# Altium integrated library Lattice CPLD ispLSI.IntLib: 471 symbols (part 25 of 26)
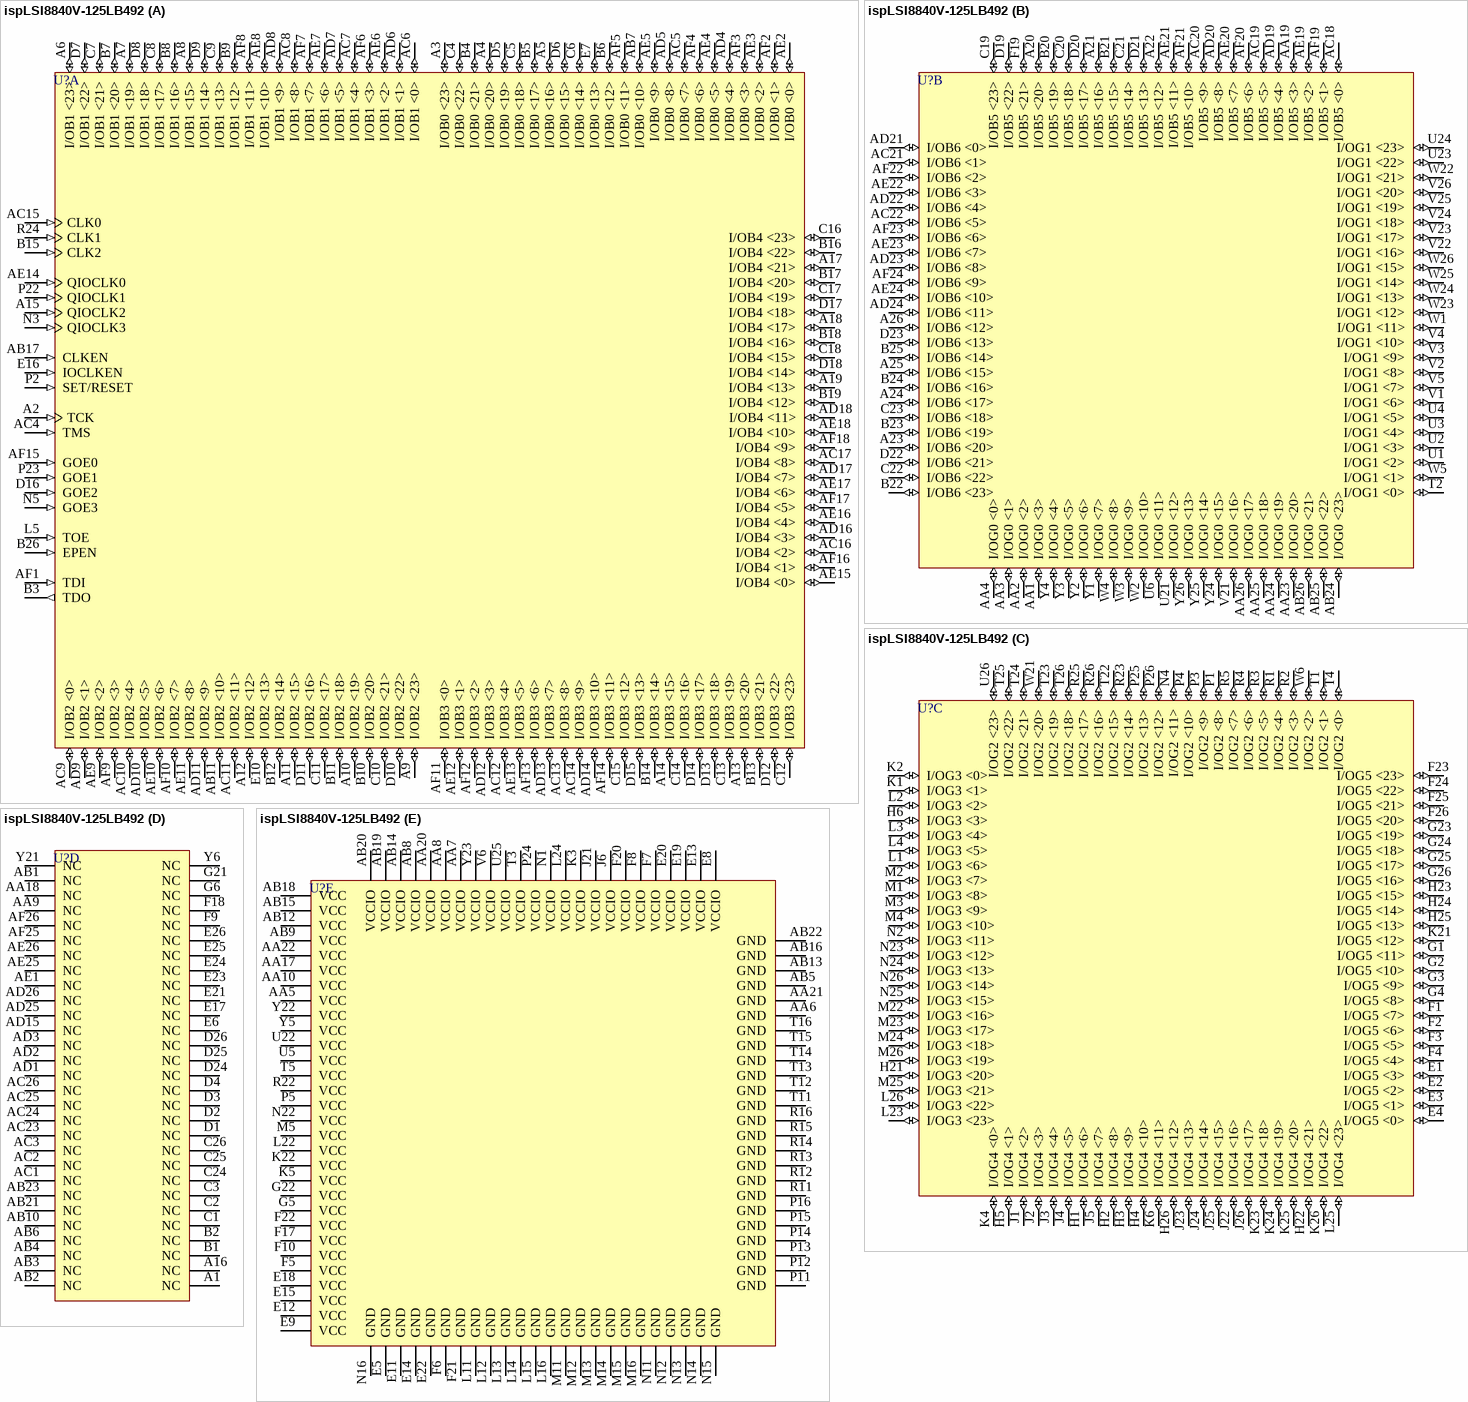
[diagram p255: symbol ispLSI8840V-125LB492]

## ispLSI8840V-125LB492
designator U?
3.3V In-System Programmable SuperBIG High Density PLD
footprint BGA492 (BGA, 492-Leads, Body 35x35mm, Pitch 1.27mm)
3D model 8840V-BGA492 (492-Ball Ball Grid Array (BGA492))
part A pins: A2 TCK (in), A3 I/OB0 <23> (io), A4 I/OB0 <20> (io), A5 I/OB0 <16> (io), A6 I/OB1 <23> (io), A7 I/OB1 <19> (io), A8 I/OB1 <15> (io), A9 I/OB2 <23> (io), A10 I/OB2 <19> (io), A11 I/OB2 <15> (io), A12 I/OB2 <12> (io), A13 I/OB3 <20> (io), A14 I/OB3 <15> (io), A15 QIOCLK2 (in), A17 I/OB4 <21> (io), A18 I/OB4 <17> (io), A19 I/OB4 <13> (io), AB7 I/OB0 <10> (io), AB11 I/OB2 <10> (io), AB17 CLKEN (in), AC4 TMS (in), AC5 I/OB0 <7> (io), AC6 I/OB1 <0> (io), AC7 I/OB1 <4> (io), AC8 I/OB1 <8> (io), AC9 I/OB2 <0> (io), AC10 I/OB2 <4> (io), AC11 I/OB2 <11> (io), AC12 I/OB3 <4> (io), AC13 I/OB3 <8> (io), AC14 I/OB3 <9> (io), AC15 CLK0 (in), AC16 I/OB4 <2> (io), AC17 I/OB4 <8> (io), AD4 I/OB0 <4> (io), AD5 I/OB0 <8> (io), AD6 I/OB1 <1> (io), AD7 I/OB1 <5> (io), AD8 I/OB1 <9> (io), AD9 I/OB2 <1> (io), AD10 I/OB2 <5> (io), AD11 I/OB2 <9> (io), AD12 I/OB3 <3> (io), AD13 I/OB3 <7> (io), AD14 I/OB3 <10> (io), AD16 I/OB4 <3> (io), AD17 I/OB4 <7> (io), AD18 I/OB4 <11> (io), AE2 I/OB0 <0> (io), AE3 I/OB0 <2> (io), AE4 I/OB0 <5> (io), AE5 I/OB0 <9> (io), AE6 I/OB1 <2> (io), AE7 I/OB1 <6> (io), AE8 I/OB1 <10> (io), AE9 I/OB2 <2> (io), AE10 I/OB2 <6> (io), AE11 I/OB2 <8> (io), AE12 I/OB3 <1> (io), AE13 I/OB3 <5> (io), AE14 QIOCLK0 (in), AE15 I/OB4 <0> (io), AE16 I/OB4 <4> (io), AE17 I/OB4 <6> (io), AE18 I/OB4 <10> (io), AF1 TDI (in), AF2 I/OB0 <1> (io), AF3 I/OB0 <3> (io), AF4 I/OB0 <6> (io), AF5 I/OB0 <11> (io), AF6 I/OB1 <3> (io), AF7 I/OB1 <7> (io), AF8 I/OB1 <11> (io), AF9 I/OB2 <3> (io), AF10 I/OB2 <7> (io), AF11 I/OB3 <0> (io), AF12 I/OB3 <2> (io), AF13 I/OB3 <6> (io), AF14 I/OB3 <11> (io), AF15 GOE0 (in), AF16 I/OB4 <1> (io), AF17 I/OB4 <5> (io), AF18 I/OB4 <9> (io), B3 TDO (out), B4 I/OB0 <21> (io), B5 I/OB0 <17> (io), B6 I/OB0 <12> (io), B7 I/OB1 <20> (io), B8 I/OB1 <16> (io), B9 I/OB1 <12> (io), B10 I/OB2 <20> (io), B11 I/OB2 <18> (io), B12 I/OB2 <14> (io), B13 I/OB3 <21> (io), B14 I/OB3 <14> (io), B15 CLK2 (in), B16 I/OB4 <22> (io), B17 I/OB4 <20> (io), B18 I/OB4 <16> (io), B19 I/OB4 <12> (io), B26 EPEN (in), C4 I/OB0 <22> (io), C5 I/OB0 <18> (io), C6 I/OB0 <14> (io), C7 I/OB1 <21> (io), C8 I/OB1 <17> (io), C9 I/OB1 <13> (io), C10 I/OB2 <21> (io), C11 I/OB2 <17> (io), C12 I/OB3 <23> (io), C13 I/OB3 <19> (io), C14 I/OB3 <16> (io), C15 I/OB3 <12> (io), C16 I/OB4 <23> (io), C17 I/OB4 <19> (io), C18 I/OB4 <15> (io), D5 I/OB0 <19> (io), D6 I/OB0 <15> (io), D7 I/OB1 <22> (io), D8 I/OB1 <18> (io), D9 I/OB1 <14> (io), D10 I/OB2 <22> (io), D11 I/OB2 <16> (io), D12 I/OB3 <22> (io), D13 I/OB3 <18> (io), D14 I/OB3 <17> (io), D15 I/OB3 <13> (io), D16 GOE2 (in), D17 I/OB4 <18> (io), D18 I/OB4 <14> (io), E7 I/OB0 <13> (io), E10 I/OB2 <13> (io), E16 IOCLKEN (in), L5 TOE (in), N3 QIOCLK3 (in), N5 GOE3 (in), P2 SET/RESET (in), P22 QIOCLK1 (in), P23 GOE1 (in), R24 CLK1 (in)
part B pins: A20 I/OB5 <20> (io), A21 I/OB5 <16> (io), A22 I/OB5 <12> (io), A23 I/OB6 <20> (io), A24 I/OB6 <17> (io), A25 I/OB6 <15> (io), A26 I/OB6 <12> (io), AA1 I/OG0 <3> (io), AA2 I/OG0 <2> (io), AA3 I/OG0 <1> (io), AA4 I/OG0 <0> (io), AA19 I/OB5 <3> (io), AA23 I/OG0 <20> (io), AA24 I/OG0 <19> (io), AA25 I/OG0 <18> (io), AA26 I/OG0 <17> (io), AB24 I/OG0 <23> (io), AB25 I/OG0 <22> (io), AB26 I/OG0 <21> (io), AC18 I/OB5 <0> (io), AC19 I/OB5 <5> (io), AC20 I/OB5 <9> (io), AC21 I/OB6 <1> (io), AC22 I/OB6 <5> (io), AD19 I/OB5 <4> (io), AD20 I/OB5 <8> (io), AD21 I/OB6 <0> (io), AD22 I/OB6 <4> (io), AD23 I/OB6 <8> (io), AD24 I/OB6 <11> (io), AE19 I/OB5 <2> (io), AE20 I/OB5 <7> (io), AE21 I/OB5 <11> (io), AE22 I/OB6 <3> (io), AE23 I/OB6 <7> (io), AE24 I/OB6 <10> (io), AF19 I/OB5 <1> (io), AF20 I/OB5 <6> (io), AF21 I/OB5 <10> (io), AF22 I/OB6 <2> (io), AF23 I/OB6 <6> (io), AF24 I/OB6 <9> (io), B20 I/OB5 <19> (io), B21 I/OB5 <15> (io), B22 I/OB6 <23> (io), B23 I/OB6 <19> (io), B24 I/OB6 <16> (io), B25 I/OB6 <14> (io), C19 I/OB5 <23> (io), C20 I/OB5 <18> (io), C21 I/OB5 <14> (io), C22 I/OB6 <22> (io), C23 I/OB6 <18> (io), D19 I/OB5 <22> (io), D20 I/OB5 <17> (io), D21 I/OB5 <13> (io), D22 I/OB6 <21> (io), D23 I/OB6 <13> (io), F19 I/OB5 <21> (io), T2 I/OG1 <0> (io), U1 I/OG1 <2> (io), U2 I/OG1 <3> (io), U3 I/OG1 <4> (io), U4 I/OG1 <5> (io), U6 I/OG0 <11> (io), U21 I/OG0 <12> (io), U23 I/OG1 <22> (io), U24 I/OG1 <23> (io), V1 I/OG1 <6> (io), V2 I/OG1 <8> (io), V3 I/OG1 <9> (io), V4 I/OG1 <10> (io), V5 I/OG1 <7> (io), V21 I/OG0 <16> (io), V22 I/OG1 <16> (io), V23 I/OG1 <17> (io), V24 I/OG1 <18> (io), V25 I/OG1 <19> (io), V26 I/OG1 <20> (io), W1 I/OG1 <11> (io), W2 I/OG0 <10> (io), W3 I/OG0 <9> (io), W4 I/OG0 <8> (io), W5 I/OG1 <1> (io), W22 I/OG1 <21> (io), W23 I/OG1 <12> (io), W24 I/OG1 <13> (io), W25 I/OG1 <14> (io), W26 I/OG1 <15> (io), Y1 I/OG0 <7> (io), Y2 I/OG0 <6> (io), Y3 I/OG0 <5> (io), Y4 I/OG0 <4> (io), Y24 I/OG0 <15> (io), Y25 I/OG0 <14> (io), Y26 I/OG0 <13> (io)
part C pins: E1 I/OG5 <3> (io), E2 I/OG5 <2> (io), E3 I/OG5 <1> (io), E4 I/OG5 <0> (io), F1 I/OG5 <7> (io), F2 I/OG5 <6> (io), F3 I/OG5 <5> (io), F4 I/OG5 <4> (io), F23 I/OG5 <23> (io), F24 I/OG5 <22> (io), F25 I/OG5 <21> (io), F26 I/OG5 <20> (io), G1 I/OG5 <11> (io), G2 I/OG5 <10> (io), G3 I/OG5 <9> (io), G4 I/OG5 <8> (io), G23 I/OG5 <19> (io), G24 I/OG5 <18> (io), G25 I/OG5 <17> (io), G26 I/OG5 <16> (io), H1 I/OG4 <6> (io), H2 I/OG4 <8> (io), H3 I/OG4 <9> (io), H4 I/OG4 <10> (io), H5 I/OG4 <1> (io), H6 I/OG3 <3> (io), H21 I/OG3 <20> (io), H22 I/OG4 <21> (io), H23 I/OG5 <15> (io), H24 I/OG5 <14> (io), H25 I/OG5 <13> (io), H26 I/OG4 <12> (io), J1 I/OG4 <2> (io), J2 I/OG4 <3> (io), J3 I/OG4 <4> (io), J4 I/OG4 <5> (io), J5 I/OG4 <7> (io), J22 I/OG4 <16> (io), J23 I/OG4 <13> (io), J24 I/OG4 <14> (io), J25 I/OG4 <15> (io), J26 I/OG4 <17> (io), K1 I/OG3 <1> (io), K2 I/OG3 <0> (io), K4 I/OG4 <0> (io), K6 I/OG4 <11> (io), K21 I/OG5 <12> (io), K23 I/OG4 <18> (io), K24 I/OG4 <19> (io), K25 I/OG4 <20> (io), K26 I/OG4 <22> (io), L1 I/OG3 <6> (io), L2 I/OG3 <2> (io), L3 I/OG3 <4> (io), L4 I/OG3 <5> (io), L23 I/OG3 <23> (io), L25 I/OG4 <23> (io), L26 I/OG3 <22> (io), M1 I/OG3 <8> (io), M2 I/OG3 <7> (io), M3 I/OG3 <9> (io), M4 I/OG3 <10> (io), M22 I/OG3 <16> (io), M23 I/OG3 <17> (io), M24 I/OG3 <18> (io), M25 I/OG3 <21> (io), M26 I/OG3 <19> (io), N2 I/OG3 <11> (io), N4 I/OG2 <11> (io), N23 I/OG3 <12> (io), N24 I/OG3 <13> (io), N25 I/OG3 <15> (io), N26 I/OG3 <14> (io), P1 I/OG2 <8> (io), P3 I/OG2 <9> (io), P4 I/OG2 <10> (io), P25 I/OG2 <13> (io), P26 I/OG2 <12> (io), R1 I/OG2 <4> (io), R2 I/OG2 <3> (io), R3 I/OG2 <5> (io), R4 I/OG2 <6> (io), R5 I/OG2 <7> (io), R23 I/OG2 <14> (io), R25 I/OG2 <17> (io), R26 I/OG2 <16> (io), T1 I/OG2 <1> (io), T4 I/OG2 <0> (io), T22 I/OG2 <15> (io), T23 I/OG2 <19> (io), T24 I/OG2 <21> (io), T25 I/OG2 <22> (io), T26 I/OG2 <18> (io), U26 I/OG2 <23> (io), W6 I/OG2 <2> (io), W21 I/OG2 <20> (io)
part D pins: A1 NC, A16 NC, AA9 NC, AA18 NC, AB1 NC, AB2 NC, AB3 NC, AB4 NC, AB6 NC, AB10 NC, AB21 NC, AB23 NC, AC1 NC, AC2 NC, AC3 NC, AC23 NC, AC24 NC, AC25 NC, AC26 NC, AD1 NC, AD2 NC, AD3 NC, AD15 NC, AD25 NC, AD26 NC, AE1 NC, AE25 NC, AE26 NC, AF25 NC, AF26 NC, B1 NC, B2 NC, C1 NC, C2 NC, C3 NC, C24 NC, C25 NC, C26 NC, D1 NC, D2 NC, D3 NC, D4 NC, D24 NC, D25 NC, D26 NC, E6 NC, E17 NC, E21 NC, E23 NC, E24 NC, E25 NC, E26 NC, F9 NC, F18 NC, G6 NC, G21 NC, Y6 NC, Y21 NC
part E pins: AA5 VCC (power), AA6 GND (power), AA7 VCCIO (power), AA8 VCCIO (power), AA10 VCC (power), AA17 VCC (power), AA20 VCCIO (power), AA21 GND (power), AA22 VCC (power), AB5 GND (power), AB8 VCCIO (power), AB9 VCC (power), AB12 VCC (power), AB13 GND (power), AB14 VCCIO (power), AB15 VCC (power), AB16 GND (power), AB18 VCC (power), AB19 VCCIO (power), AB20 VCCIO (power), AB22 GND (power), E5 GND (power), E8 VCCIO (power), E9 VCC (power), E11 GND (power), E12 VCC (power), E13 VCCIO (power), E14 GND (power), E15 VCC (power), E18 VCC (power), E19 VCCIO (power), E20 VCCIO (power), E22 GND (power), F5 VCC (power), F6 GND (power), F7 VCCIO (power), F8 VCCIO (power), F10 VCC (power), F17 VCC (power), F20 VCCIO (power), F21 GND (power), F22 VCC (power), G5 VCC (power), G22 VCC (power), J6 VCCIO (power), J21 VCCIO (power), K3 VCCIO (power), K5 VCC (power), K22 VCC (power), L11 GND (power), L12 GND (power), L13 GND (power), L14 GND (power), L15 GND (power), L16 GND (power), L22 VCC (power), L24 VCCIO (power), M5 VCC (power), M11 GND (power), M12 GND (power), M13 GND (power), M14 GND (power), M15 GND (power), M16 GND (power), N1 VCCIO (power), N11 GND (power), N12 GND (power), N13 GND (power), N14 GND (power), N15 GND (power), N16 GND (power), N22 VCC (power), P5 VCC (power), P11 GND (power), P12 GND (power), P13 GND (power), P14 GND (power), P15 GND (power), P16 GND (power), P24 VCCIO (power), R11 GND (power), R12 GND (power), R13 GND (power), R14 GND (power), R15 GND (power), R16 GND (power), R22 VCC (power), T3 VCCIO (power), T5 VCC (power), T11 GND (power), T12 GND (power), T13 GND (power), T14 GND (power), T15 GND (power), T16 GND (power), U5 VCC (power), U22 VCC (power), U25 VCCIO (power), V6 VCCIO (power), Y5 VCC (power), Y22 VCC (power), Y23 VCCIO (power)

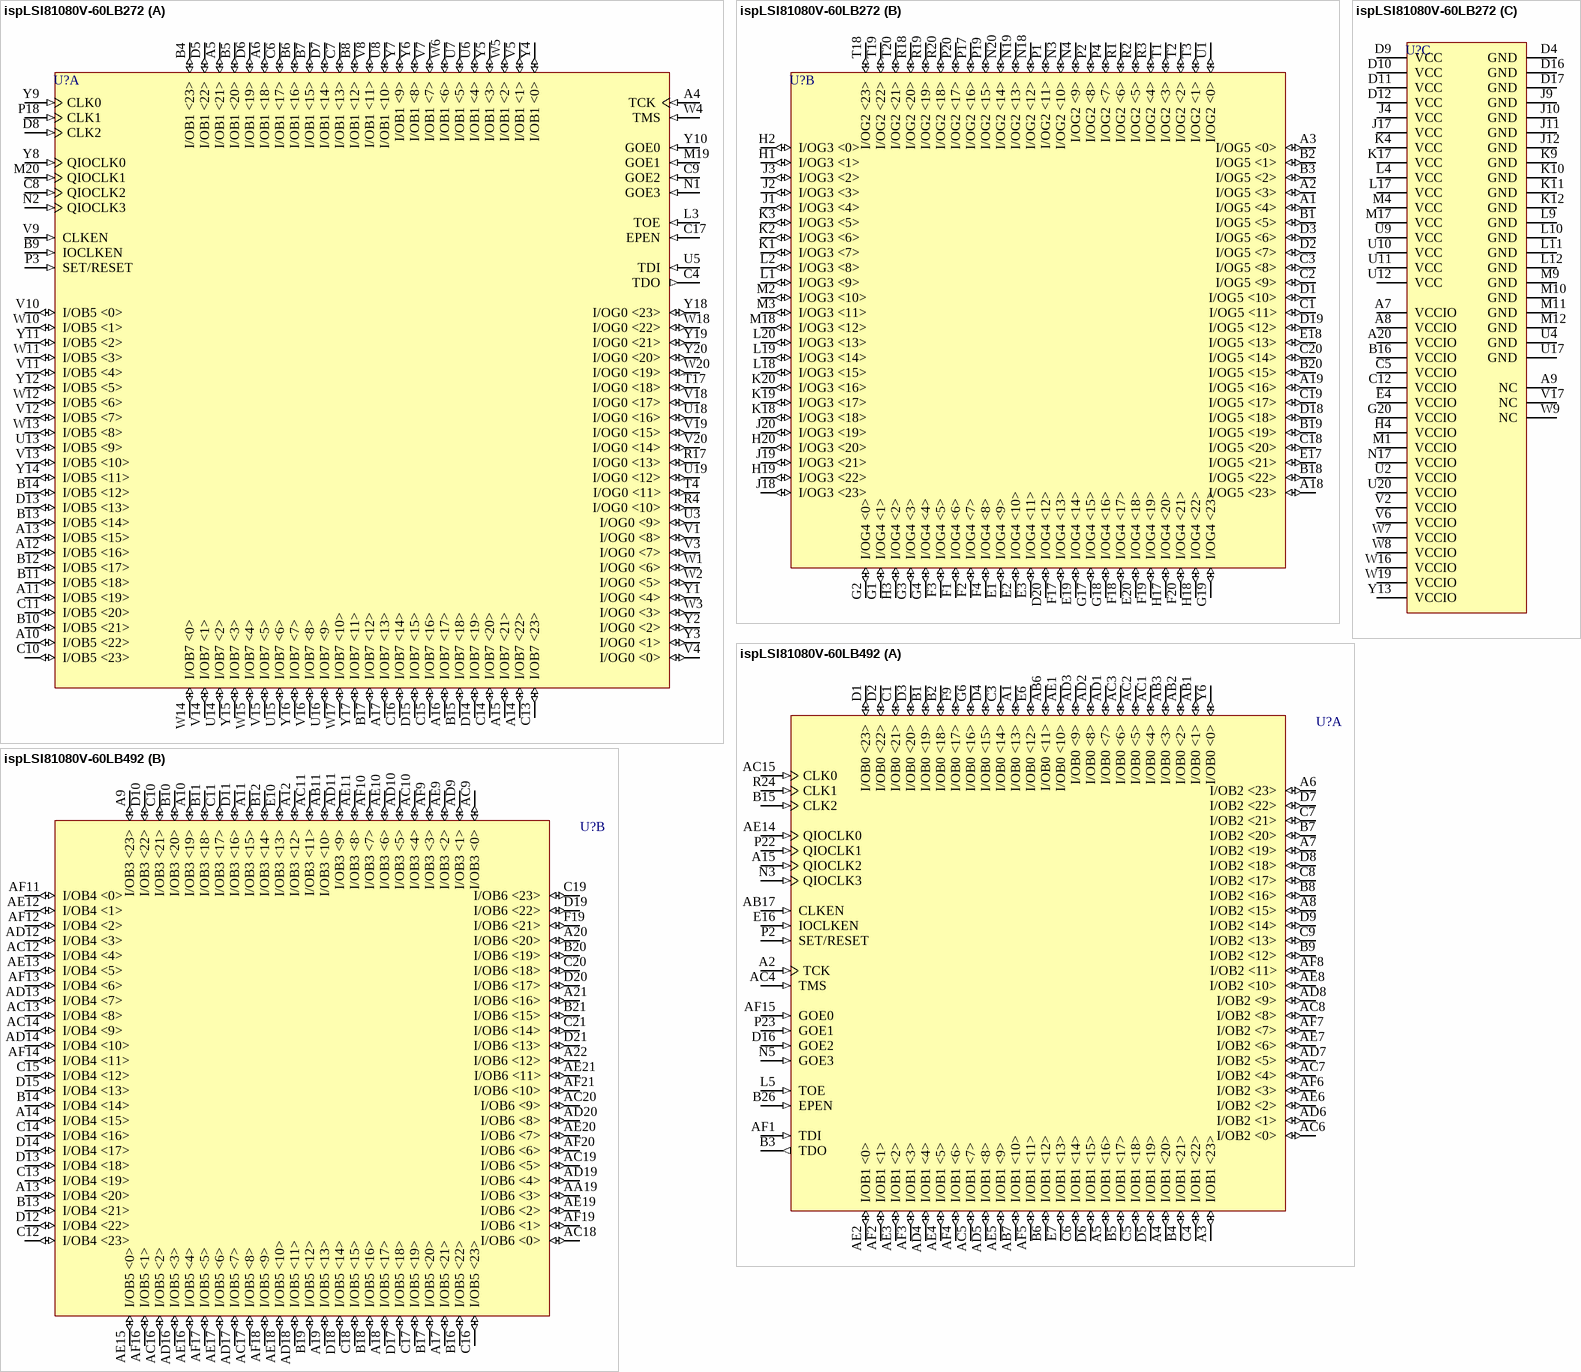
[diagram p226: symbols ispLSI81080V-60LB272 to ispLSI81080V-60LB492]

## ispLSI81080V-60LB272
designator U?
3.3V In-System Programmable SuperBIG High Density PLD
footprint BGA272 (BGA, 272-Leads, Body 27x27mm, Pitch 1.27mm)
3D model 81080V-BGA272 (272-Ball Ball Grid Array (BGA272))
part A pins: A4 TCK (in), A5 I/OB1 <21> (io), A6 I/OB1 <18> (io), A10 I/OB5 <22> (io), A11 I/OB5 <19> (io), A12 I/OB5 <16> (io), A13 I/OB5 <15> (io), A14 I/OB7 <22> (io), A15 I/OB7 <21> (io), A16 I/OB7 <17> (io), A17 I/OB7 <13> (io), B4 I/OB1 <23> (io), B5 I/OB1 <20> (io), B6 I/OB1 <16> (io), B7 I/OB1 <15> (io), B8 I/OB1 <12> (io), B9 IOCLKEN (in), B10 I/OB5 <21> (io), B11 I/OB5 <18> (io), B12 I/OB5 <17> (io), B13 I/OB5 <14> (io), B14 I/OB5 <12> (io), B15 I/OB7 <18> (io), B17 I/OB7 <12> (io), C4 TDO (out), C6 I/OB1 <17> (io), C7 I/OB1 <13> (io), C8 QIOCLK2 (in), C9 GOE2 (in), C10 I/OB5 <23> (io), C11 I/OB5 <20> (io), C13 I/OB7 <23> (io), C14 I/OB7 <20> (io), C15 I/OB7 <16> (io), C16 I/OB7 <14> (io), C17 EPEN (in), D5 I/OB1 <22> (io), D6 I/OB1 <19> (io), D7 I/OB1 <14> (io), D8 CLK2 (in), D13 I/OB5 <13> (io), D14 I/OB7 <19> (io), D15 I/OB7 <15> (io), L3 TOE (in), M19 GOE1 (in), M20 QIOCLK1 (in), N1 GOE3 (in), N2 QIOCLK3 (in), P3 SET/RESET (in), P18 CLK1 (in), R4 I/OG0 <10> (io), R17 I/OG0 <13> (io), T4 I/OG0 <11> (io), T17 I/OG0 <18> (io), U3 I/OG0 <9> (io), U5 TDI (in), U6 I/OB1 <4> (io), U7 I/OB1 <5> (io), U8 I/OB1 <10> (io), U13 I/OB5 <9> (io), U14 I/OB7 <2> (io), U15 I/OB7 <6> (io), U16 I/OB7 <9> (io), U18 I/OG0 <16> (io), U19 I/OG0 <12> (io), V1 I/OG0 <8> (io), V3 I/OG0 <7> (io), V4 I/OG0 <0> (io), V5 I/OB1 <1> (io), V7 I/OB1 <7> (io), V8 I/OB1 <11> (io), V9 CLKEN (in), V10 I/OB5 <0> (io), V11 I/OB5 <4> (io), V12 I/OB5 <7> (io), V13 I/OB5 <10> (io), V14 I/OB7 <1> (io), V15 I/OB7 <5> (io), V16 I/OB7 <8> (io), V18 I/OG0 <17> (io), V19 I/OG0 <15> (io), V20 I/OG0 <14> (io), W1 I/OG0 <6> (io), W2 I/OG0 <5> (io), W3 I/OG0 <3> (io), W4 TMS (in), W5 I/OB1 <2> (io), W6 I/OB1 <6> (io), W10 I/OB5 <1> (io), W11 I/OB5 <3> (io), W12 I/OB5 <6> (io), W13 I/OB5 <8> (io), W14 I/OB7 <0> (io), W15 I/OB7 <4> (io), W17 I/OB7 <10> (io), W18 I/OG0 <22> (io), W20 I/OG0 <19> (io), Y1 I/OG0 <4> (io), Y2 I/OG0 <2> (io), Y3 I/OG0 <1> (io), Y4 I/OB1 <0> (io), Y5 I/OB1 <3> (io), Y6 I/OB1 <8> (io), Y7 I/OB1 <9> (io), Y8 QIOCLK0 (in), Y9 CLK0 (in), Y10 GOE0 (in), Y11 I/OB5 <2> (io), Y12 I/OB5 <5> (io), Y14 I/OB5 <11> (io), Y15 I/OB7 <3> (io), Y16 I/OB7 <7> (io), Y17 I/OB7 <11> (io), Y18 I/OG0 <23> (io), Y19 I/OG0 <21> (io), Y20 I/OG0 <20> (io)
part B pins: A1 I/OG5 <4> (io), A2 I/OG5 <3> (io), A3 I/OG5 <0> (io), A18 I/OG5 <23> (io), A19 I/OG5 <16> (io), B1 I/OG5 <5> (io), B2 I/OG5 <1> (io), B3 I/OG5 <2> (io), B18 I/OG5 <22> (io), B19 I/OG5 <19> (io), B20 I/OG5 <15> (io), C1 I/OG5 <11> (io), C2 I/OG5 <9> (io), C3 I/OG5 <8> (io), C18 I/OG5 <20> (io), C19 I/OG5 <17> (io), C20 I/OG5 <14> (io), D1 I/OG5 <10> (io), D2 I/OG5 <7> (io), D3 I/OG5 <6> (io), D18 I/OG5 <18> (io), D19 I/OG5 <12> (io), D20 I/OG4 <12> (io), E1 I/OG4 <9> (io), E2 I/OG4 <10> (io), E3 I/OG4 <11> (io), E17 I/OG5 <21> (io), E18 I/OG5 <13> (io), E19 I/OG4 <14> (io), E20 I/OG4 <18> (io), F1 I/OG4 <6> (io), F2 I/OG4 <7> (io), F3 I/OG4 <5> (io), F4 I/OG4 <8> (io), F17 I/OG4 <13> (io), F18 I/OG4 <17> (io), F19 I/OG4 <19> (io), F20 I/OG4 <21> (io), G1 I/OG4 <1> (io), G2 I/OG4 <0> (io), G3 I/OG4 <3> (io), G4 I/OG4 <4> (io), G17 I/OG4 <15> (io), G18 I/OG4 <16> (io), G19 I/OG4 <23> (io), H1 I/OG3 <1> (io), H2 I/OG3 <0> (io), H3 I/OG4 <2> (io), H17 I/OG4 <20> (io), H18 I/OG4 <22> (io), H19 I/OG3 <22> (io), H20 I/OG3 <20> (io), J1 I/OG3 <4> (io), J2 I/OG3 <3> (io), J3 I/OG3 <2> (io), J18 I/OG3 <23> (io), J19 I/OG3 <21> (io), J20 I/OG3 <19> (io), K1 I/OG3 <7> (io), K2 I/OG3 <6> (io), K3 I/OG3 <5> (io), K18 I/OG3 <18> (io), K19 I/OG3 <17> (io), K20 I/OG3 <16> (io), L1 I/OG3 <9> (io), L2 I/OG3 <8> (io), L18 I/OG3 <15> (io), L19 I/OG3 <14> (io), L20 I/OG3 <13> (io), M2 I/OG3 <10> (io), M3 I/OG3 <11> (io), M18 I/OG3 <12> (io), N3 I/OG2 <10> (io), N4 I/OG2 <9> (io), N18 I/OG2 <12> (io), N19 I/OG2 <13> (io), N20 I/OG2 <14> (io), P1 I/OG2 <11> (io), P2 I/OG2 <8> (io), P4 I/OG2 <7> (io), P17 I/OG2 <16> (io), P19 I/OG2 <15> (io), P20 I/OG2 <17> (io), R1 I/OG2 <6> (io), R2 I/OG2 <5> (io), R3 I/OG2 <4> (io), R18 I/OG2 <20> (io), R19 I/OG2 <19> (io), R20 I/OG2 <18> (io), T1 I/OG2 <3> (io), T2 I/OG2 <2> (io), T3 I/OG2 <1> (io), T18 I/OG2 <23> (io), T19 I/OG2 <22> (io), T20 I/OG2 <21> (io), U1 I/OG2 <0> (io)
part C pins: A7 VCCIO (power), A8 VCCIO (power), A9 NC, A20 VCCIO (power), B16 VCCIO (power), C5 VCCIO (power), C12 VCCIO (power), D4 GND (power), D9 VCC (power), D10 VCC (power), D11 VCC (power), D12 VCC (power), D16 GND (power), D17 GND (power), E4 VCCIO (power), G20 VCCIO (power), H4 VCCIO (power), J4 VCC (power), J9 GND (power), J10 GND (power), J11 GND (power), J12 GND (power), J17 VCC (power), K4 VCC (power), K9 GND (power), K10 GND (power), K11 GND (power), K12 GND (power), K17 VCC (power), L4 VCC (power), L9 GND (power), L10 GND (power), L11 GND (power), L12 GND (power), L17 VCC (power), M1 VCCIO (power), M4 VCC (power), M9 GND (power), M10 GND (power), M11 GND (power), M12 GND (power), M17 VCC (power), N17 VCCIO (power), U2 VCCIO (power), U4 GND (power), U9 VCC (power), U10 VCC (power), U11 VCC (power), U12 VCC (power), U17 GND (power), U20 VCCIO (power), V2 VCCIO (power), V6 VCCIO (power), V17 NC, W7 VCCIO (power), W8 VCCIO (power), W9 NC, W16 VCCIO (power), W19 VCCIO (power), Y13 VCCIO (power)

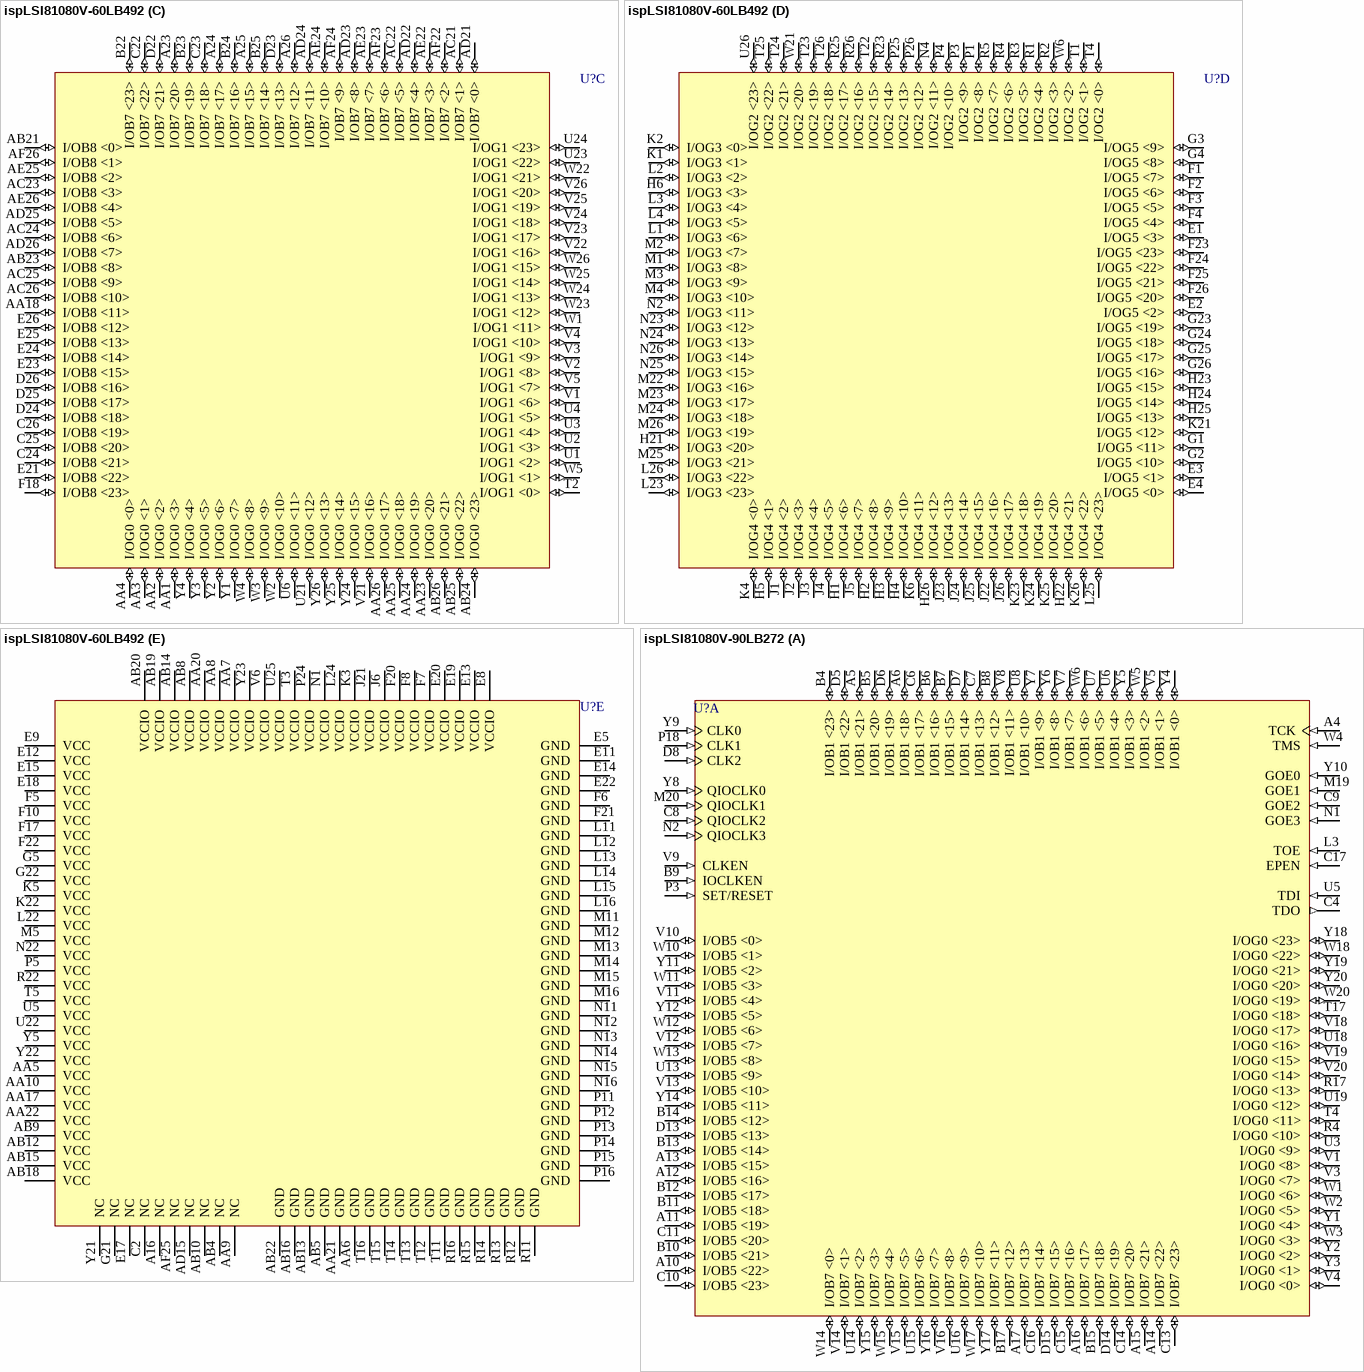
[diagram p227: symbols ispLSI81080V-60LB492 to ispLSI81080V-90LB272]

## ispLSI81080V-60LB492
designator U?
3.3V In-System Programmable SuperBIG High Density PLD
footprint BGA492 (BGA, 492-Leads, Body 35x35mm, Pitch 1.27mm)
3D model 81080V-BGA492 (492-Ball Ball Grid Array (BGA492))
part A pins: A1 I/OB0 <13> (io), A2 TCK (in), A3 I/OB1 <23> (io), A4 I/OB1 <20> (io), A5 I/OB1 <16> (io), A6 I/OB2 <23> (io), A7 I/OB2 <19> (io), A8 I/OB2 <15> (io), A15 QIOCLK2 (in), AB1 I/OB0 <1> (io), AB2 I/OB0 <2> (io), AB3 I/OB0 <3> (io), AB6 I/OB0 <11> (io), AB7 I/OB1 <10> (io), AB17 CLKEN (in), AC1 I/OB0 <4> (io), AC2 I/OB0 <5> (io), AC3 I/OB0 <6> (io), AC4 TMS (in), AC5 I/OB1 <7> (io), AC6 I/OB2 <0> (io), AC7 I/OB2 <4> (io), AC8 I/OB2 <8> (io), AC15 CLK0 (in), AD1 I/OB0 <7> (io), AD2 I/OB0 <8> (io), AD3 I/OB0 <9> (io), AD4 I/OB1 <4> (io), AD5 I/OB1 <8> (io), AD6 I/OB2 <1> (io), AD7 I/OB2 <5> (io), AD8 I/OB2 <9> (io), AE1 I/OB0 <10> (io), AE2 I/OB1 <0> (io), AE3 I/OB1 <2> (io), AE4 I/OB1 <5> (io), AE5 I/OB1 <9> (io), AE6 I/OB2 <2> (io), AE7 I/OB2 <6> (io), AE8 I/OB2 <10> (io), AE14 QIOCLK0 (in), AF1 TDI (in), AF2 I/OB1 <1> (io), AF3 I/OB1 <3> (io), AF4 I/OB1 <6> (io), AF5 I/OB1 <11> (io), AF6 I/OB2 <3> (io), AF7 I/OB2 <7> (io), AF8 I/OB2 <11> (io), AF15 GOE0 (in), B1 I/OB0 <19> (io), B2 I/OB0 <18> (io), B3 TDO (out), B4 I/OB1 <21> (io), B5 I/OB1 <17> (io), B6 I/OB1 <12> (io), B7 I/OB2 <20> (io), B8 I/OB2 <16> (io), B9 I/OB2 <12> (io), B15 CLK2 (in), B26 EPEN (in), C1 I/OB0 <21> (io), C3 I/OB0 <14> (io), C4 I/OB1 <22> (io), C5 I/OB1 <18> (io), C6 I/OB1 <14> (io), C7 I/OB2 <21> (io), C8 I/OB2 <17> (io), C9 I/OB2 <13> (io), D1 I/OB0 <23> (io), D2 I/OB0 <22> (io), D3 I/OB0 <20> (io), D4 I/OB0 <15> (io), D5 I/OB1 <19> (io), D6 I/OB1 <15> (io), D7 I/OB2 <22> (io), D8 I/OB2 <18> (io), D9 I/OB2 <14> (io), D16 GOE2 (in), E6 I/OB0 <12> (io), E7 I/OB1 <13> (io), E16 IOCLKEN (in), F9 I/OB0 <17> (io), G6 I/OB0 <16> (io), L5 TOE (in), N3 QIOCLK3 (in), N5 GOE3 (in), P2 SET/RESET (in), P22 QIOCLK1 (in), P23 GOE1 (in), R24 CLK1 (in), Y6 I/OB0 <0> (io)
part B pins: A9 I/OB3 <23> (io), A10 I/OB3 <19> (io), A11 I/OB3 <15> (io), A12 I/OB3 <12> (io), A13 I/OB4 <20> (io), A14 I/OB4 <15> (io), A17 I/OB5 <21> (io), A18 I/OB5 <17> (io), A19 I/OB5 <13> (io), A20 I/OB6 <20> (io), A21 I/OB6 <16> (io), A22 I/OB6 <12> (io), AA19 I/OB6 <3> (io), AB11 I/OB3 <10> (io), AC9 I/OB3 <0> (io), AC10 I/OB3 <4> (io), AC11 I/OB3 <11> (io), AC12 I/OB4 <4> (io), AC13 I/OB4 <8> (io), AC14 I/OB4 <9> (io), AC16 I/OB5 <2> (io), AC17 I/OB5 <8> (io), AC18 I/OB6 <0> (io), AC19 I/OB6 <5> (io), AC20 I/OB6 <9> (io), AD9 I/OB3 <1> (io), AD10 I/OB3 <5> (io), AD11 I/OB3 <9> (io), AD12 I/OB4 <3> (io), AD13 I/OB4 <7> (io), AD14 I/OB4 <10> (io), AD16 I/OB5 <3> (io), AD17 I/OB5 <7> (io), AD18 I/OB5 <11> (io), AD19 I/OB6 <4> (io), AD20 I/OB6 <8> (io), AE9 I/OB3 <2> (io), AE10 I/OB3 <6> (io), AE11 I/OB3 <8> (io), AE12 I/OB4 <1> (io), AE13 I/OB4 <5> (io), AE15 I/OB5 <0> (io), AE16 I/OB5 <4> (io), AE17 I/OB5 <6> (io), AE18 I/OB5 <10> (io), AE19 I/OB6 <2> (io), AE20 I/OB6 <7> (io), AE21 I/OB6 <11> (io), AF9 I/OB3 <3> (io), AF10 I/OB3 <7> (io), AF11 I/OB4 <0> (io), AF12 I/OB4 <2> (io), AF13 I/OB4 <6> (io), AF14 I/OB4 <11> (io), AF16 I/OB5 <1> (io), AF17 I/OB5 <5> (io), AF18 I/OB5 <9> (io), AF19 I/OB6 <1> (io), AF20 I/OB6 <6> (io), AF21 I/OB6 <10> (io), B10 I/OB3 <20> (io), B11 I/OB3 <18> (io), B12 I/OB3 <14> (io), B13 I/OB4 <21> (io), B14 I/OB4 <14> (io), B16 I/OB5 <22> (io), B17 I/OB5 <20> (io), B18 I/OB5 <16> (io), B19 I/OB5 <12> (io), B20 I/OB6 <19> (io), B21 I/OB6 <15> (io), C10 I/OB3 <21> (io), C11 I/OB3 <17> (io), C12 I/OB4 <23> (io), C13 I/OB4 <19> (io), C14 I/OB4 <16> (io), C15 I/OB4 <12> (io), C16 I/OB5 <23> (io), C17 I/OB5 <19> (io), C18 I/OB5 <15> (io), C19 I/OB6 <23> (io), C20 I/OB6 <18> (io), C21 I/OB6 <14> (io), D10 I/OB3 <22> (io), D11 I/OB3 <16> (io), D12 I/OB4 <22> (io), D13 I/OB4 <18> (io), D14 I/OB4 <17> (io), D15 I/OB4 <13> (io), D17 I/OB5 <18> (io), D18 I/OB5 <14> (io), D19 I/OB6 <22> (io), D20 I/OB6 <17> (io), D21 I/OB6 <13> (io), E10 I/OB3 <13> (io), F19 I/OB6 <21> (io)
part C pins: A23 I/OB7 <20> (io), A24 I/OB7 <17> (io), A25 I/OB7 <15> (io), A26 I/OB7 <12> (io), AA1 I/OG0 <3> (io), AA2 I/OG0 <2> (io), AA3 I/OG0 <1> (io), AA4 I/OG0 <0> (io), AA18 I/OB8 <11> (io), AA23 I/OG0 <20> (io), AA24 I/OG0 <19> (io), AA25 I/OG0 <18> (io), AA26 I/OG0 <17> (io), AB21 I/OB8 <0> (io), AB23 I/OB8 <8> (io), AB24 I/OG0 <23> (io), AB25 I/OG0 <22> (io), AB26 I/OG0 <21> (io), AC21 I/OB7 <1> (io), AC22 I/OB7 <5> (io), AC23 I/OB8 <3> (io), AC24 I/OB8 <6> (io), AC25 I/OB8 <9> (io), AC26 I/OB8 <10> (io), AD21 I/OB7 <0> (io), AD22 I/OB7 <4> (io), AD23 I/OB7 <8> (io), AD24 I/OB7 <11> (io), AD25 I/OB8 <5> (io), AD26 I/OB8 <7> (io), AE22 I/OB7 <3> (io), AE23 I/OB7 <7> (io), AE24 I/OB7 <10> (io), AE25 I/OB8 <2> (io), AE26 I/OB8 <4> (io), AF22 I/OB7 <2> (io), AF23 I/OB7 <6> (io), AF24 I/OB7 <9> (io), AF26 I/OB8 <1> (io), B22 I/OB7 <23> (io), B23 I/OB7 <19> (io), B24 I/OB7 <16> (io), B25 I/OB7 <14> (io), C22 I/OB7 <22> (io), C23 I/OB7 <18> (io), C24 I/OB8 <21> (io), C25 I/OB8 <20> (io), C26 I/OB8 <19> (io), D22 I/OB7 <21> (io), D23 I/OB7 <13> (io), D24 I/OB8 <18> (io), D25 I/OB8 <17> (io), D26 I/OB8 <16> (io), E21 I/OB8 <22> (io), E23 I/OB8 <15> (io), E24 I/OB8 <14> (io), E25 I/OB8 <13> (io), E26 I/OB8 <12> (io), F18 I/OB8 <23> (io), T2 I/OG1 <0> (io), U1 I/OG1 <2> (io), U2 I/OG1 <3> (io), U3 I/OG1 <4> (io), U4 I/OG1 <5> (io), U6 I/OG0 <11> (io), U21 I/OG0 <12> (io), U23 I/OG1 <22> (io), U24 I/OG1 <23> (io), V1 I/OG1 <6> (io), V2 I/OG1 <8> (io), V3 I/OG1 <9> (io), V4 I/OG1 <10> (io), V5 I/OG1 <7> (io), V21 I/OG0 <16> (io), V22 I/OG1 <16> (io), V23 I/OG1 <17> (io), V24 I/OG1 <18> (io), V25 I/OG1 <19> (io), V26 I/OG1 <20> (io), W1 I/OG1 <11> (io), W2 I/OG0 <10> (io), W3 I/OG0 <9> (io), W4 I/OG0 <8> (io), W5 I/OG1 <1> (io), W22 I/OG1 <21> (io), W23 I/OG1 <12> (io), W24 I/OG1 <13> (io), W25 I/OG1 <14> (io), W26 I/OG1 <15> (io), Y1 I/OG0 <7> (io), Y2 I/OG0 <6> (io), Y3 I/OG0 <5> (io), Y4 I/OG0 <4> (io), Y24 I/OG0 <15> (io), Y25 I/OG0 <14> (io), Y26 I/OG0 <13> (io)
part D pins: E1 I/OG5 <3> (io), E2 I/OG5 <2> (io), E3 I/OG5 <1> (io), E4 I/OG5 <0> (io), F1 I/OG5 <7> (io), F2 I/OG5 <6> (io), F3 I/OG5 <5> (io), F4 I/OG5 <4> (io), F23 I/OG5 <23> (io), F24 I/OG5 <22> (io), F25 I/OG5 <21> (io), F26 I/OG5 <20> (io), G1 I/OG5 <11> (io), G2 I/OG5 <10> (io), G3 I/OG5 <9> (io), G4 I/OG5 <8> (io), G23 I/OG5 <19> (io), G24 I/OG5 <18> (io), G25 I/OG5 <17> (io), G26 I/OG5 <16> (io), H1 I/OG4 <6> (io), H2 I/OG4 <8> (io), H3 I/OG4 <9> (io), H4 I/OG4 <10> (io), H5 I/OG4 <1> (io), H6 I/OG3 <3> (io), H21 I/OG3 <20> (io), H22 I/OG4 <21> (io), H23 I/OG5 <15> (io), H24 I/OG5 <14> (io), H25 I/OG5 <13> (io), H26 I/OG4 <12> (io), J1 I/OG4 <2> (io), J2 I/OG4 <3> (io), J3 I/OG4 <4> (io), J4 I/OG4 <5> (io), J5 I/OG4 <7> (io), J22 I/OG4 <16> (io), J23 I/OG4 <13> (io), J24 I/OG4 <14> (io), J25 I/OG4 <15> (io), J26 I/OG4 <17> (io), K1 I/OG3 <1> (io), K2 I/OG3 <0> (io), K4 I/OG4 <0> (io), K6 I/OG4 <11> (io), K21 I/OG5 <12> (io), K23 I/OG4 <18> (io), K24 I/OG4 <19> (io), K25 I/OG4 <20> (io), K26 I/OG4 <22> (io), L1 I/OG3 <6> (io), L2 I/OG3 <2> (io), L3 I/OG3 <4> (io), L4 I/OG3 <5> (io), L23 I/OG3 <23> (io), L25 I/OG4 <23> (io), L26 I/OG3 <22> (io), M1 I/OG3 <8> (io), M2 I/OG3 <7> (io), M3 I/OG3 <9> (io), M4 I/OG3 <10> (io), M22 I/OG3 <16> (io), M23 I/OG3 <17> (io), M24 I/OG3 <18> (io), M25 I/OG3 <21> (io), M26 I/OG3 <19> (io), N2 I/OG3 <11> (io), N4 I/OG2 <11> (io), N23 I/OG3 <12> (io), N24 I/OG3 <13> (io), N25 I/OG3 <15> (io), N26 I/OG3 <14> (io), P1 I/OG2 <8> (io), P3 I/OG2 <9> (io), P4 I/OG2 <10> (io), P25 I/OG2 <13> (io), P26 I/OG2 <12> (io), R1 I/OG2 <4> (io), R2 I/OG2 <3> (io), R3 I/OG2 <5> (io), R4 I/OG2 <6> (io), R5 I/OG2 <7> (io), R23 I/OG2 <14> (io), R25 I/OG2 <17> (io), R26 I/OG2 <16> (io), T1 I/OG2 <1> (io), T4 I/OG2 <0> (io), T22 I/OG2 <15> (io), T23 I/OG2 <19> (io), T24 I/OG2 <21> (io), T25 I/OG2 <22> (io), T26 I/OG2 <18> (io), U26 I/OG2 <23> (io), W6 I/OG2 <2> (io), W21 I/OG2 <20> (io)
part E pins: A16 NC, AA5 VCC (power), AA6 GND (power), AA7 VCCIO (power), AA8 VCCIO (power), AA9 NC, AA10 VCC (power), AA17 VCC (power), AA20 VCCIO (power), AA21 GND (power), AA22 VCC (power), AB4 NC, AB5 GND (power), AB8 VCCIO (power), AB9 VCC (power), AB10 NC, AB12 VCC (power), AB13 GND (power), AB14 VCCIO (power), AB15 VCC (power), AB16 GND (power), AB18 VCC (power), AB19 VCCIO (power), AB20 VCCIO (power), AB22 GND (power), AD15 NC, AF25 NC, C2 NC, E5 GND (power), E8 VCCIO (power), E9 VCC (power), E11 GND (power), E12 VCC (power), E13 VCCIO (power), E14 GND (power), E15 VCC (power), E17 NC, E18 VCC (power), E19 VCCIO (power), E20 VCCIO (power), E22 GND (power), F5 VCC (power), F6 GND (power), F7 VCCIO (power), F8 VCCIO (power), F10 VCC (power), F17 VCC (power), F20 VCCIO (power), F21 GND (power), F22 VCC (power), G5 VCC (power), G21 NC, G22 VCC (power), J6 VCCIO (power), J21 VCCIO (power), K3 VCCIO (power), K5 VCC (power), K22 VCC (power), L11 GND (power), L12 GND (power), L13 GND (power), L14 GND (power), L15 GND (power), L16 GND (power), L22 VCC (power), L24 VCCIO (power), M5 VCC (power), M11 GND (power), M12 GND (power), M13 GND (power), M14 GND (power), M15 GND (power), M16 GND (power), N1 VCCIO (power), N11 GND (power), N12 GND (power), N13 GND (power), N14 GND (power), N15 GND (power), N16 GND (power), N22 VCC (power), P5 VCC (power), P11 GND (power), P12 GND (power), P13 GND (power), P14 GND (power), P15 GND (power), P16 GND (power), P24 VCCIO (power), R11 GND (power), R12 GND (power), R13 GND (power), R14 GND (power), R15 GND (power), R16 GND (power), R22 VCC (power), T3 VCCIO (power), T5 VCC (power), T11 GND (power), T12 GND (power), T13 GND (power), T14 GND (power), T15 GND (power), T16 GND (power), U5 VCC (power), U22 VCC (power), U25 VCCIO (power), V6 VCCIO (power), Y5 VCC (power), Y21 NC, Y22 VCC (power), Y23 VCCIO (power)

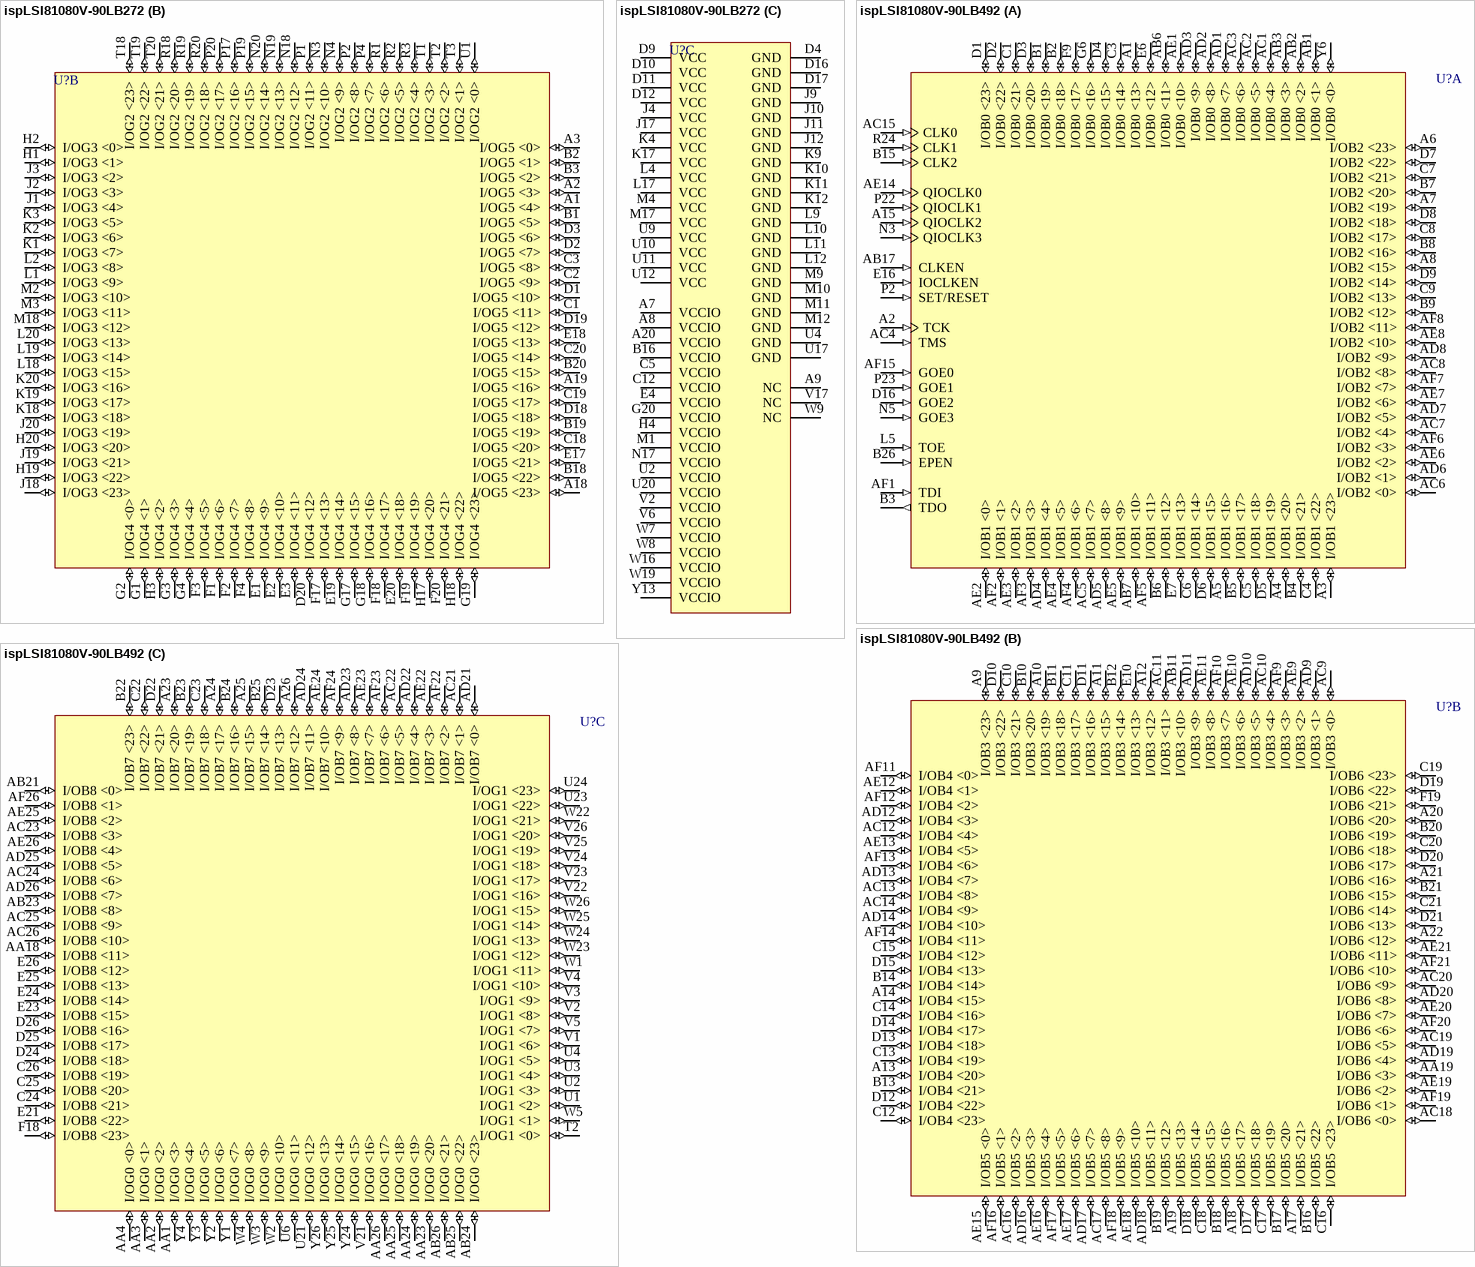
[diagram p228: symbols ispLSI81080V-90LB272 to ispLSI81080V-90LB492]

## ispLSI81080V-90LB272
designator U?
3.3V In-System Programmable SuperBIG High Density PLD
footprint BGA272 (BGA, 272-Leads, Body 27x27mm, Pitch 1.27mm)
3D model 81080V-BGA272 (272-Ball Ball Grid Array (BGA272))
part A pins: A4 TCK (in), A5 I/OB1 <21> (io), A6 I/OB1 <18> (io), A10 I/OB5 <22> (io), A11 I/OB5 <19> (io), A12 I/OB5 <16> (io), A13 I/OB5 <15> (io), A14 I/OB7 <22> (io), A15 I/OB7 <21> (io), A16 I/OB7 <17> (io), A17 I/OB7 <13> (io), B4 I/OB1 <23> (io), B5 I/OB1 <20> (io), B6 I/OB1 <16> (io), B7 I/OB1 <15> (io), B8 I/OB1 <12> (io), B9 IOCLKEN (in), B10 I/OB5 <21> (io), B11 I/OB5 <18> (io), B12 I/OB5 <17> (io), B13 I/OB5 <14> (io), B14 I/OB5 <12> (io), B15 I/OB7 <18> (io), B17 I/OB7 <12> (io), C4 TDO (out), C6 I/OB1 <17> (io), C7 I/OB1 <13> (io), C8 QIOCLK2 (in), C9 GOE2 (in), C10 I/OB5 <23> (io), C11 I/OB5 <20> (io), C13 I/OB7 <23> (io), C14 I/OB7 <20> (io), C15 I/OB7 <16> (io), C16 I/OB7 <14> (io), C17 EPEN (in), D5 I/OB1 <22> (io), D6 I/OB1 <19> (io), D7 I/OB1 <14> (io), D8 CLK2 (in), D13 I/OB5 <13> (io), D14 I/OB7 <19> (io), D15 I/OB7 <15> (io), L3 TOE (in), M19 GOE1 (in), M20 QIOCLK1 (in), N1 GOE3 (in), N2 QIOCLK3 (in), P3 SET/RESET (in), P18 CLK1 (in), R4 I/OG0 <10> (io), R17 I/OG0 <13> (io), T4 I/OG0 <11> (io), T17 I/OG0 <18> (io), U3 I/OG0 <9> (io), U5 TDI (in), U6 I/OB1 <4> (io), U7 I/OB1 <5> (io), U8 I/OB1 <10> (io), U13 I/OB5 <9> (io), U14 I/OB7 <2> (io), U15 I/OB7 <6> (io), U16 I/OB7 <9> (io), U18 I/OG0 <16> (io), U19 I/OG0 <12> (io), V1 I/OG0 <8> (io), V3 I/OG0 <7> (io), V4 I/OG0 <0> (io), V5 I/OB1 <1> (io), V7 I/OB1 <7> (io), V8 I/OB1 <11> (io), V9 CLKEN (in), V10 I/OB5 <0> (io), V11 I/OB5 <4> (io), V12 I/OB5 <7> (io), V13 I/OB5 <10> (io), V14 I/OB7 <1> (io), V15 I/OB7 <5> (io), V16 I/OB7 <8> (io), V18 I/OG0 <17> (io), V19 I/OG0 <15> (io), V20 I/OG0 <14> (io), W1 I/OG0 <6> (io), W2 I/OG0 <5> (io), W3 I/OG0 <3> (io), W4 TMS (in), W5 I/OB1 <2> (io), W6 I/OB1 <6> (io), W10 I/OB5 <1> (io), W11 I/OB5 <3> (io), W12 I/OB5 <6> (io), W13 I/OB5 <8> (io), W14 I/OB7 <0> (io), W15 I/OB7 <4> (io), W17 I/OB7 <10> (io), W18 I/OG0 <22> (io), W20 I/OG0 <19> (io), Y1 I/OG0 <4> (io), Y2 I/OG0 <2> (io), Y3 I/OG0 <1> (io), Y4 I/OB1 <0> (io), Y5 I/OB1 <3> (io), Y6 I/OB1 <8> (io), Y7 I/OB1 <9> (io), Y8 QIOCLK0 (in), Y9 CLK0 (in), Y10 GOE0 (in), Y11 I/OB5 <2> (io), Y12 I/OB5 <5> (io), Y14 I/OB5 <11> (io), Y15 I/OB7 <3> (io), Y16 I/OB7 <7> (io), Y17 I/OB7 <11> (io), Y18 I/OG0 <23> (io), Y19 I/OG0 <21> (io), Y20 I/OG0 <20> (io)
part B pins: A1 I/OG5 <4> (io), A2 I/OG5 <3> (io), A3 I/OG5 <0> (io), A18 I/OG5 <23> (io), A19 I/OG5 <16> (io), B1 I/OG5 <5> (io), B2 I/OG5 <1> (io), B3 I/OG5 <2> (io), B18 I/OG5 <22> (io), B19 I/OG5 <19> (io), B20 I/OG5 <15> (io), C1 I/OG5 <11> (io), C2 I/OG5 <9> (io), C3 I/OG5 <8> (io), C18 I/OG5 <20> (io), C19 I/OG5 <17> (io), C20 I/OG5 <14> (io), D1 I/OG5 <10> (io), D2 I/OG5 <7> (io), D3 I/OG5 <6> (io), D18 I/OG5 <18> (io), D19 I/OG5 <12> (io), D20 I/OG4 <12> (io), E1 I/OG4 <9> (io), E2 I/OG4 <10> (io), E3 I/OG4 <11> (io), E17 I/OG5 <21> (io), E18 I/OG5 <13> (io), E19 I/OG4 <14> (io), E20 I/OG4 <18> (io), F1 I/OG4 <6> (io), F2 I/OG4 <7> (io), F3 I/OG4 <5> (io), F4 I/OG4 <8> (io), F17 I/OG4 <13> (io), F18 I/OG4 <17> (io), F19 I/OG4 <19> (io), F20 I/OG4 <21> (io), G1 I/OG4 <1> (io), G2 I/OG4 <0> (io), G3 I/OG4 <3> (io), G4 I/OG4 <4> (io), G17 I/OG4 <15> (io), G18 I/OG4 <16> (io), G19 I/OG4 <23> (io), H1 I/OG3 <1> (io), H2 I/OG3 <0> (io), H3 I/OG4 <2> (io), H17 I/OG4 <20> (io), H18 I/OG4 <22> (io), H19 I/OG3 <22> (io), H20 I/OG3 <20> (io), J1 I/OG3 <4> (io), J2 I/OG3 <3> (io), J3 I/OG3 <2> (io), J18 I/OG3 <23> (io), J19 I/OG3 <21> (io), J20 I/OG3 <19> (io), K1 I/OG3 <7> (io), K2 I/OG3 <6> (io), K3 I/OG3 <5> (io), K18 I/OG3 <18> (io), K19 I/OG3 <17> (io), K20 I/OG3 <16> (io), L1 I/OG3 <9> (io), L2 I/OG3 <8> (io), L18 I/OG3 <15> (io), L19 I/OG3 <14> (io), L20 I/OG3 <13> (io), M2 I/OG3 <10> (io), M3 I/OG3 <11> (io), M18 I/OG3 <12> (io), N3 I/OG2 <10> (io), N4 I/OG2 <9> (io), N18 I/OG2 <12> (io), N19 I/OG2 <13> (io), N20 I/OG2 <14> (io), P1 I/OG2 <11> (io), P2 I/OG2 <8> (io), P4 I/OG2 <7> (io), P17 I/OG2 <16> (io), P19 I/OG2 <15> (io), P20 I/OG2 <17> (io), R1 I/OG2 <6> (io), R2 I/OG2 <5> (io), R3 I/OG2 <4> (io), R18 I/OG2 <20> (io), R19 I/OG2 <19> (io), R20 I/OG2 <18> (io), T1 I/OG2 <3> (io), T2 I/OG2 <2> (io), T3 I/OG2 <1> (io), T18 I/OG2 <23> (io), T19 I/OG2 <22> (io), T20 I/OG2 <21> (io), U1 I/OG2 <0> (io)
part C pins: A7 VCCIO (power), A8 VCCIO (power), A9 NC, A20 VCCIO (power), B16 VCCIO (power), C5 VCCIO (power), C12 VCCIO (power), D4 GND (power), D9 VCC (power), D10 VCC (power), D11 VCC (power), D12 VCC (power), D16 GND (power), D17 GND (power), E4 VCCIO (power), G20 VCCIO (power), H4 VCCIO (power), J4 VCC (power), J9 GND (power), J10 GND (power), J11 GND (power), J12 GND (power), J17 VCC (power), K4 VCC (power), K9 GND (power), K10 GND (power), K11 GND (power), K12 GND (power), K17 VCC (power), L4 VCC (power), L9 GND (power), L10 GND (power), L11 GND (power), L12 GND (power), L17 VCC (power), M1 VCCIO (power), M4 VCC (power), M9 GND (power), M10 GND (power), M11 GND (power), M12 GND (power), M17 VCC (power), N17 VCCIO (power), U2 VCCIO (power), U4 GND (power), U9 VCC (power), U10 VCC (power), U11 VCC (power), U12 VCC (power), U17 GND (power), U20 VCCIO (power), V2 VCCIO (power), V6 VCCIO (power), V17 NC, W7 VCCIO (power), W8 VCCIO (power), W9 NC, W16 VCCIO (power), W19 VCCIO (power), Y13 VCCIO (power)

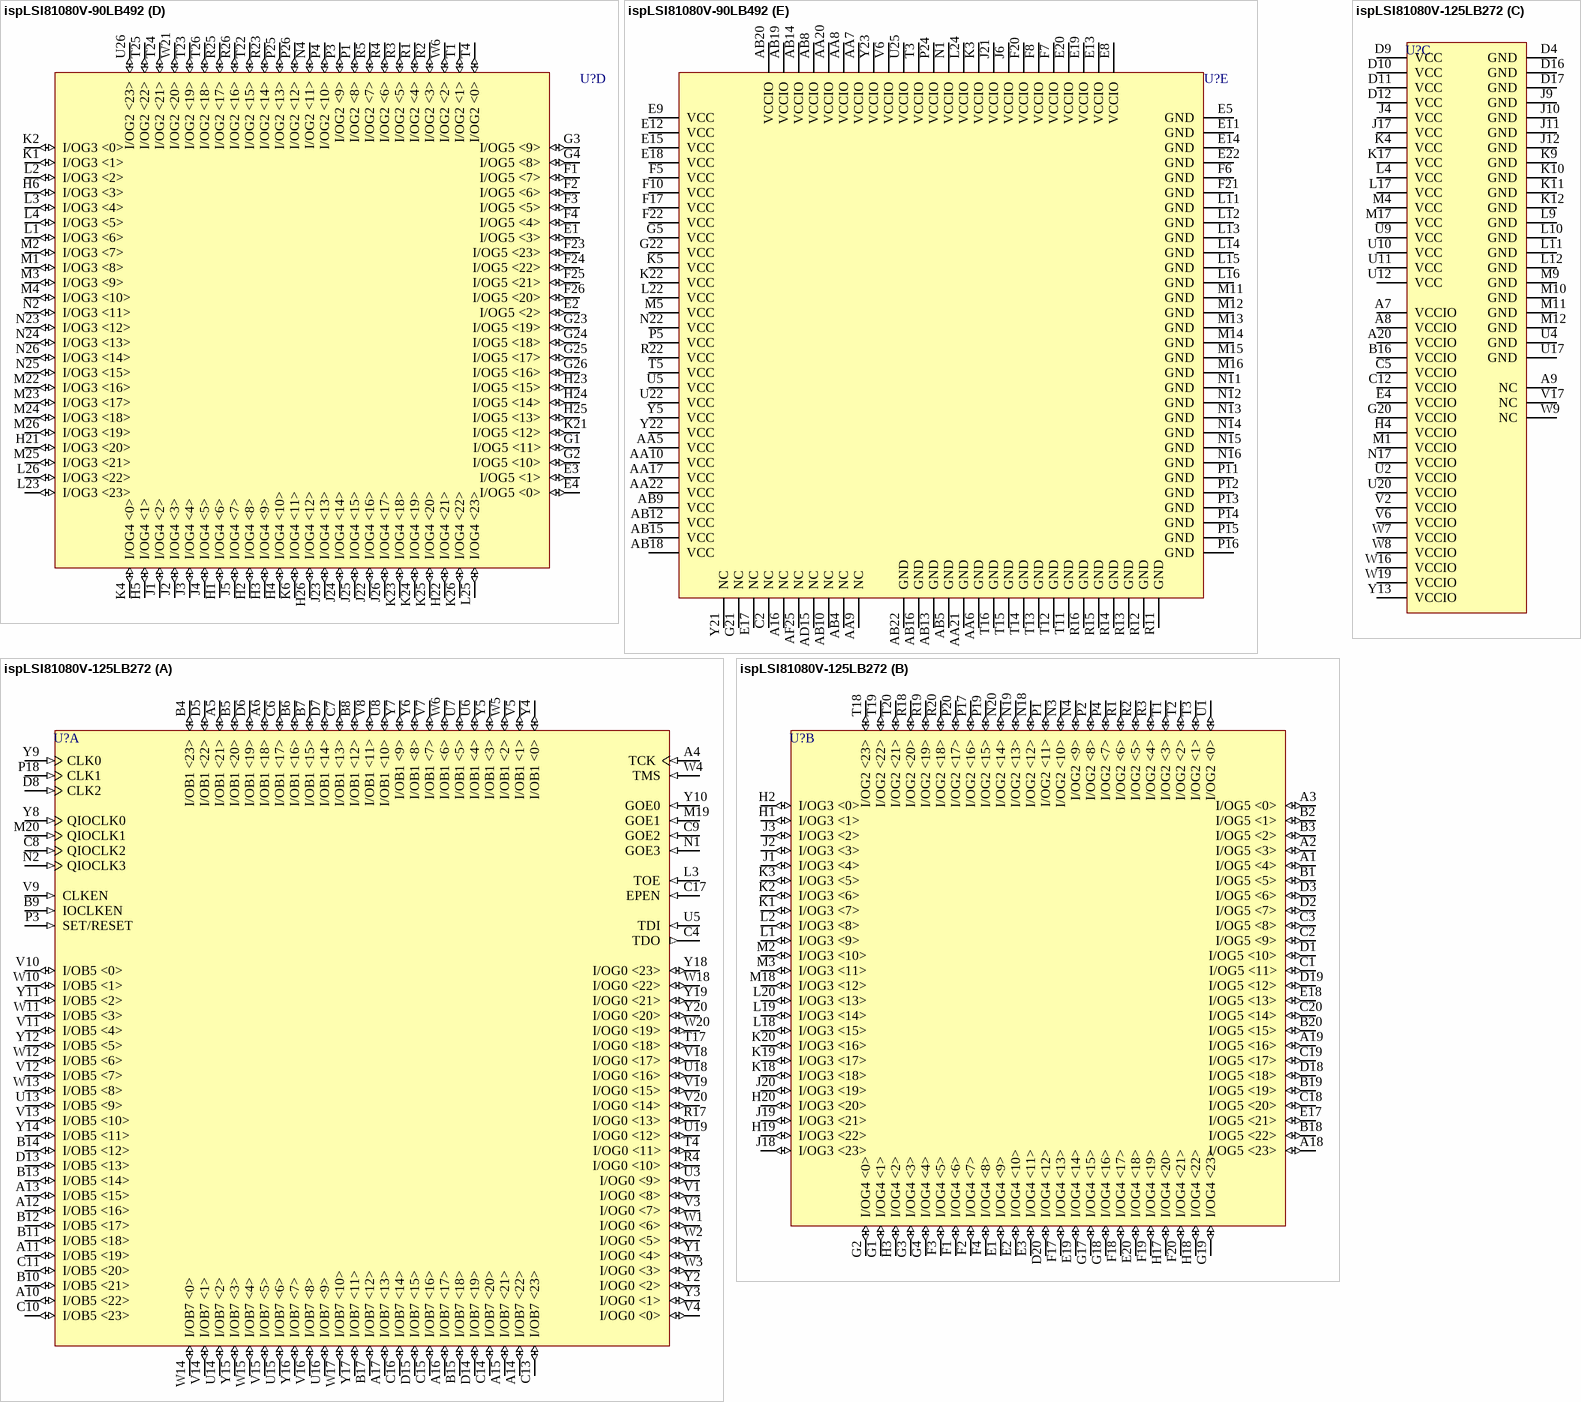
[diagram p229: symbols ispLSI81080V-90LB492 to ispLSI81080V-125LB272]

## ispLSI81080V-90LB492
designator U?
3.3V In-System Programmable SuperBIG High Density PLD
footprint BGA492 (BGA, 492-Leads, Body 35x35mm, Pitch 1.27mm)
3D model 81080V-BGA492 (492-Ball Ball Grid Array (BGA492))
part A pins: A1 I/OB0 <13> (io), A2 TCK (in), A3 I/OB1 <23> (io), A4 I/OB1 <20> (io), A5 I/OB1 <16> (io), A6 I/OB2 <23> (io), A7 I/OB2 <19> (io), A8 I/OB2 <15> (io), A15 QIOCLK2 (in), AB1 I/OB0 <1> (io), AB2 I/OB0 <2> (io), AB3 I/OB0 <3> (io), AB6 I/OB0 <11> (io), AB7 I/OB1 <10> (io), AB17 CLKEN (in), AC1 I/OB0 <4> (io), AC2 I/OB0 <5> (io), AC3 I/OB0 <6> (io), AC4 TMS (in), AC5 I/OB1 <7> (io), AC6 I/OB2 <0> (io), AC7 I/OB2 <4> (io), AC8 I/OB2 <8> (io), AC15 CLK0 (in), AD1 I/OB0 <7> (io), AD2 I/OB0 <8> (io), AD3 I/OB0 <9> (io), AD4 I/OB1 <4> (io), AD5 I/OB1 <8> (io), AD6 I/OB2 <1> (io), AD7 I/OB2 <5> (io), AD8 I/OB2 <9> (io), AE1 I/OB0 <10> (io), AE2 I/OB1 <0> (io), AE3 I/OB1 <2> (io), AE4 I/OB1 <5> (io), AE5 I/OB1 <9> (io), AE6 I/OB2 <2> (io), AE7 I/OB2 <6> (io), AE8 I/OB2 <10> (io), AE14 QIOCLK0 (in), AF1 TDI (in), AF2 I/OB1 <1> (io), AF3 I/OB1 <3> (io), AF4 I/OB1 <6> (io), AF5 I/OB1 <11> (io), AF6 I/OB2 <3> (io), AF7 I/OB2 <7> (io), AF8 I/OB2 <11> (io), AF15 GOE0 (in), B1 I/OB0 <19> (io), B2 I/OB0 <18> (io), B3 TDO (out), B4 I/OB1 <21> (io), B5 I/OB1 <17> (io), B6 I/OB1 <12> (io), B7 I/OB2 <20> (io), B8 I/OB2 <16> (io), B9 I/OB2 <12> (io), B15 CLK2 (in), B26 EPEN (in), C1 I/OB0 <21> (io), C3 I/OB0 <14> (io), C4 I/OB1 <22> (io), C5 I/OB1 <18> (io), C6 I/OB1 <14> (io), C7 I/OB2 <21> (io), C8 I/OB2 <17> (io), C9 I/OB2 <13> (io), D1 I/OB0 <23> (io), D2 I/OB0 <22> (io), D3 I/OB0 <20> (io), D4 I/OB0 <15> (io), D5 I/OB1 <19> (io), D6 I/OB1 <15> (io), D7 I/OB2 <22> (io), D8 I/OB2 <18> (io), D9 I/OB2 <14> (io), D16 GOE2 (in), E6 I/OB0 <12> (io), E7 I/OB1 <13> (io), E16 IOCLKEN (in), F9 I/OB0 <17> (io), G6 I/OB0 <16> (io), L5 TOE (in), N3 QIOCLK3 (in), N5 GOE3 (in), P2 SET/RESET (in), P22 QIOCLK1 (in), P23 GOE1 (in), R24 CLK1 (in), Y6 I/OB0 <0> (io)
part B pins: A9 I/OB3 <23> (io), A10 I/OB3 <19> (io), A11 I/OB3 <15> (io), A12 I/OB3 <12> (io), A13 I/OB4 <20> (io), A14 I/OB4 <15> (io), A17 I/OB5 <21> (io), A18 I/OB5 <17> (io), A19 I/OB5 <13> (io), A20 I/OB6 <20> (io), A21 I/OB6 <16> (io), A22 I/OB6 <12> (io), AA19 I/OB6 <3> (io), AB11 I/OB3 <10> (io), AC9 I/OB3 <0> (io), AC10 I/OB3 <4> (io), AC11 I/OB3 <11> (io), AC12 I/OB4 <4> (io), AC13 I/OB4 <8> (io), AC14 I/OB4 <9> (io), AC16 I/OB5 <2> (io), AC17 I/OB5 <8> (io), AC18 I/OB6 <0> (io), AC19 I/OB6 <5> (io), AC20 I/OB6 <9> (io), AD9 I/OB3 <1> (io), AD10 I/OB3 <5> (io), AD11 I/OB3 <9> (io), AD12 I/OB4 <3> (io), AD13 I/OB4 <7> (io), AD14 I/OB4 <10> (io), AD16 I/OB5 <3> (io), AD17 I/OB5 <7> (io), AD18 I/OB5 <11> (io), AD19 I/OB6 <4> (io), AD20 I/OB6 <8> (io), AE9 I/OB3 <2> (io), AE10 I/OB3 <6> (io), AE11 I/OB3 <8> (io), AE12 I/OB4 <1> (io), AE13 I/OB4 <5> (io), AE15 I/OB5 <0> (io), AE16 I/OB5 <4> (io), AE17 I/OB5 <6> (io), AE18 I/OB5 <10> (io), AE19 I/OB6 <2> (io), AE20 I/OB6 <7> (io), AE21 I/OB6 <11> (io), AF9 I/OB3 <3> (io), AF10 I/OB3 <7> (io), AF11 I/OB4 <0> (io), AF12 I/OB4 <2> (io), AF13 I/OB4 <6> (io), AF14 I/OB4 <11> (io), AF16 I/OB5 <1> (io), AF17 I/OB5 <5> (io), AF18 I/OB5 <9> (io), AF19 I/OB6 <1> (io), AF20 I/OB6 <6> (io), AF21 I/OB6 <10> (io), B10 I/OB3 <20> (io), B11 I/OB3 <18> (io), B12 I/OB3 <14> (io), B13 I/OB4 <21> (io), B14 I/OB4 <14> (io), B16 I/OB5 <22> (io), B17 I/OB5 <20> (io), B18 I/OB5 <16> (io), B19 I/OB5 <12> (io), B20 I/OB6 <19> (io), B21 I/OB6 <15> (io), C10 I/OB3 <21> (io), C11 I/OB3 <17> (io), C12 I/OB4 <23> (io), C13 I/OB4 <19> (io), C14 I/OB4 <16> (io), C15 I/OB4 <12> (io), C16 I/OB5 <23> (io), C17 I/OB5 <19> (io), C18 I/OB5 <15> (io), C19 I/OB6 <23> (io), C20 I/OB6 <18> (io), C21 I/OB6 <14> (io), D10 I/OB3 <22> (io), D11 I/OB3 <16> (io), D12 I/OB4 <22> (io), D13 I/OB4 <18> (io), D14 I/OB4 <17> (io), D15 I/OB4 <13> (io), D17 I/OB5 <18> (io), D18 I/OB5 <14> (io), D19 I/OB6 <22> (io), D20 I/OB6 <17> (io), D21 I/OB6 <13> (io), E10 I/OB3 <13> (io), F19 I/OB6 <21> (io)
part C pins: A23 I/OB7 <20> (io), A24 I/OB7 <17> (io), A25 I/OB7 <15> (io), A26 I/OB7 <12> (io), AA1 I/OG0 <3> (io), AA2 I/OG0 <2> (io), AA3 I/OG0 <1> (io), AA4 I/OG0 <0> (io), AA18 I/OB8 <11> (io), AA23 I/OG0 <20> (io), AA24 I/OG0 <19> (io), AA25 I/OG0 <18> (io), AA26 I/OG0 <17> (io), AB21 I/OB8 <0> (io), AB23 I/OB8 <8> (io), AB24 I/OG0 <23> (io), AB25 I/OG0 <22> (io), AB26 I/OG0 <21> (io), AC21 I/OB7 <1> (io), AC22 I/OB7 <5> (io), AC23 I/OB8 <3> (io), AC24 I/OB8 <6> (io), AC25 I/OB8 <9> (io), AC26 I/OB8 <10> (io), AD21 I/OB7 <0> (io), AD22 I/OB7 <4> (io), AD23 I/OB7 <8> (io), AD24 I/OB7 <11> (io), AD25 I/OB8 <5> (io), AD26 I/OB8 <7> (io), AE22 I/OB7 <3> (io), AE23 I/OB7 <7> (io), AE24 I/OB7 <10> (io), AE25 I/OB8 <2> (io), AE26 I/OB8 <4> (io), AF22 I/OB7 <2> (io), AF23 I/OB7 <6> (io), AF24 I/OB7 <9> (io), AF26 I/OB8 <1> (io), B22 I/OB7 <23> (io), B23 I/OB7 <19> (io), B24 I/OB7 <16> (io), B25 I/OB7 <14> (io), C22 I/OB7 <22> (io), C23 I/OB7 <18> (io), C24 I/OB8 <21> (io), C25 I/OB8 <20> (io), C26 I/OB8 <19> (io), D22 I/OB7 <21> (io), D23 I/OB7 <13> (io), D24 I/OB8 <18> (io), D25 I/OB8 <17> (io), D26 I/OB8 <16> (io), E21 I/OB8 <22> (io), E23 I/OB8 <15> (io), E24 I/OB8 <14> (io), E25 I/OB8 <13> (io), E26 I/OB8 <12> (io), F18 I/OB8 <23> (io), T2 I/OG1 <0> (io), U1 I/OG1 <2> (io), U2 I/OG1 <3> (io), U3 I/OG1 <4> (io), U4 I/OG1 <5> (io), U6 I/OG0 <11> (io), U21 I/OG0 <12> (io), U23 I/OG1 <22> (io), U24 I/OG1 <23> (io), V1 I/OG1 <6> (io), V2 I/OG1 <8> (io), V3 I/OG1 <9> (io), V4 I/OG1 <10> (io), V5 I/OG1 <7> (io), V21 I/OG0 <16> (io), V22 I/OG1 <16> (io), V23 I/OG1 <17> (io), V24 I/OG1 <18> (io), V25 I/OG1 <19> (io), V26 I/OG1 <20> (io), W1 I/OG1 <11> (io), W2 I/OG0 <10> (io), W3 I/OG0 <9> (io), W4 I/OG0 <8> (io), W5 I/OG1 <1> (io), W22 I/OG1 <21> (io), W23 I/OG1 <12> (io), W24 I/OG1 <13> (io), W25 I/OG1 <14> (io), W26 I/OG1 <15> (io), Y1 I/OG0 <7> (io), Y2 I/OG0 <6> (io), Y3 I/OG0 <5> (io), Y4 I/OG0 <4> (io), Y24 I/OG0 <15> (io), Y25 I/OG0 <14> (io), Y26 I/OG0 <13> (io)
part D pins: E1 I/OG5 <3> (io), E2 I/OG5 <2> (io), E3 I/OG5 <1> (io), E4 I/OG5 <0> (io), F1 I/OG5 <7> (io), F2 I/OG5 <6> (io), F3 I/OG5 <5> (io), F4 I/OG5 <4> (io), F23 I/OG5 <23> (io), F24 I/OG5 <22> (io), F25 I/OG5 <21> (io), F26 I/OG5 <20> (io), G1 I/OG5 <11> (io), G2 I/OG5 <10> (io), G3 I/OG5 <9> (io), G4 I/OG5 <8> (io), G23 I/OG5 <19> (io), G24 I/OG5 <18> (io), G25 I/OG5 <17> (io), G26 I/OG5 <16> (io), H1 I/OG4 <6> (io), H2 I/OG4 <8> (io), H3 I/OG4 <9> (io), H4 I/OG4 <10> (io), H5 I/OG4 <1> (io), H6 I/OG3 <3> (io), H21 I/OG3 <20> (io), H22 I/OG4 <21> (io), H23 I/OG5 <15> (io), H24 I/OG5 <14> (io), H25 I/OG5 <13> (io), H26 I/OG4 <12> (io), J1 I/OG4 <2> (io), J2 I/OG4 <3> (io), J3 I/OG4 <4> (io), J4 I/OG4 <5> (io), J5 I/OG4 <7> (io), J22 I/OG4 <16> (io), J23 I/OG4 <13> (io), J24 I/OG4 <14> (io), J25 I/OG4 <15> (io), J26 I/OG4 <17> (io), K1 I/OG3 <1> (io), K2 I/OG3 <0> (io), K4 I/OG4 <0> (io), K6 I/OG4 <11> (io), K21 I/OG5 <12> (io), K23 I/OG4 <18> (io), K24 I/OG4 <19> (io), K25 I/OG4 <20> (io), K26 I/OG4 <22> (io), L1 I/OG3 <6> (io), L2 I/OG3 <2> (io), L3 I/OG3 <4> (io), L4 I/OG3 <5> (io), L23 I/OG3 <23> (io), L25 I/OG4 <23> (io), L26 I/OG3 <22> (io), M1 I/OG3 <8> (io), M2 I/OG3 <7> (io), M3 I/OG3 <9> (io), M4 I/OG3 <10> (io), M22 I/OG3 <16> (io), M23 I/OG3 <17> (io), M24 I/OG3 <18> (io), M25 I/OG3 <21> (io), M26 I/OG3 <19> (io), N2 I/OG3 <11> (io), N4 I/OG2 <11> (io), N23 I/OG3 <12> (io), N24 I/OG3 <13> (io), N25 I/OG3 <15> (io), N26 I/OG3 <14> (io), P1 I/OG2 <8> (io), P3 I/OG2 <9> (io), P4 I/OG2 <10> (io), P25 I/OG2 <13> (io), P26 I/OG2 <12> (io), R1 I/OG2 <4> (io), R2 I/OG2 <3> (io), R3 I/OG2 <5> (io), R4 I/OG2 <6> (io), R5 I/OG2 <7> (io), R23 I/OG2 <14> (io), R25 I/OG2 <17> (io), R26 I/OG2 <16> (io), T1 I/OG2 <1> (io), T4 I/OG2 <0> (io), T22 I/OG2 <15> (io), T23 I/OG2 <19> (io), T24 I/OG2 <21> (io), T25 I/OG2 <22> (io), T26 I/OG2 <18> (io), U26 I/OG2 <23> (io), W6 I/OG2 <2> (io), W21 I/OG2 <20> (io)
part E pins: A16 NC, AA5 VCC (power), AA6 GND (power), AA7 VCCIO (power), AA8 VCCIO (power), AA9 NC, AA10 VCC (power), AA17 VCC (power), AA20 VCCIO (power), AA21 GND (power), AA22 VCC (power), AB4 NC, AB5 GND (power), AB8 VCCIO (power), AB9 VCC (power), AB10 NC, AB12 VCC (power), AB13 GND (power), AB14 VCCIO (power), AB15 VCC (power), AB16 GND (power), AB18 VCC (power), AB19 VCCIO (power), AB20 VCCIO (power), AB22 GND (power), AD15 NC, AF25 NC, C2 NC, E5 GND (power), E8 VCCIO (power), E9 VCC (power), E11 GND (power), E12 VCC (power), E13 VCCIO (power), E14 GND (power), E15 VCC (power), E17 NC, E18 VCC (power), E19 VCCIO (power), E20 VCCIO (power), E22 GND (power), F5 VCC (power), F6 GND (power), F7 VCCIO (power), F8 VCCIO (power), F10 VCC (power), F17 VCC (power), F20 VCCIO (power), F21 GND (power), F22 VCC (power), G5 VCC (power), G21 NC, G22 VCC (power), J6 VCCIO (power), J21 VCCIO (power), K3 VCCIO (power), K5 VCC (power), K22 VCC (power), L11 GND (power), L12 GND (power), L13 GND (power), L14 GND (power), L15 GND (power), L16 GND (power), L22 VCC (power), L24 VCCIO (power), M5 VCC (power), M11 GND (power), M12 GND (power), M13 GND (power), M14 GND (power), M15 GND (power), M16 GND (power), N1 VCCIO (power), N11 GND (power), N12 GND (power), N13 GND (power), N14 GND (power), N15 GND (power), N16 GND (power), N22 VCC (power), P5 VCC (power), P11 GND (power), P12 GND (power), P13 GND (power), P14 GND (power), P15 GND (power), P16 GND (power), P24 VCCIO (power), R11 GND (power), R12 GND (power), R13 GND (power), R14 GND (power), R15 GND (power), R16 GND (power), R22 VCC (power), T3 VCCIO (power), T5 VCC (power), T11 GND (power), T12 GND (power), T13 GND (power), T14 GND (power), T15 GND (power), T16 GND (power), U5 VCC (power), U22 VCC (power), U25 VCCIO (power), V6 VCCIO (power), Y5 VCC (power), Y21 NC, Y22 VCC (power), Y23 VCCIO (power)

## ispLSI81080V-125LB272
designator U?
3.3V In-System Programmable SuperBIG High Density PLD
footprint BGA272 (BGA, 272-Leads, Body 27x27mm, Pitch 1.27mm)
3D model 81080V-BGA272 (272-Ball Ball Grid Array (BGA272))
part A pins: A4 TCK (in), A5 I/OB1 <21> (io), A6 I/OB1 <18> (io), A10 I/OB5 <22> (io), A11 I/OB5 <19> (io), A12 I/OB5 <16> (io), A13 I/OB5 <15> (io), A14 I/OB7 <22> (io), A15 I/OB7 <21> (io), A16 I/OB7 <17> (io), A17 I/OB7 <13> (io), B4 I/OB1 <23> (io), B5 I/OB1 <20> (io), B6 I/OB1 <16> (io), B7 I/OB1 <15> (io), B8 I/OB1 <12> (io), B9 IOCLKEN (in), B10 I/OB5 <21> (io), B11 I/OB5 <18> (io), B12 I/OB5 <17> (io), B13 I/OB5 <14> (io), B14 I/OB5 <12> (io), B15 I/OB7 <18> (io), B17 I/OB7 <12> (io), C4 TDO (out), C6 I/OB1 <17> (io), C7 I/OB1 <13> (io), C8 QIOCLK2 (in), C9 GOE2 (in), C10 I/OB5 <23> (io), C11 I/OB5 <20> (io), C13 I/OB7 <23> (io), C14 I/OB7 <20> (io), C15 I/OB7 <16> (io), C16 I/OB7 <14> (io), C17 EPEN (in), D5 I/OB1 <22> (io), D6 I/OB1 <19> (io), D7 I/OB1 <14> (io), D8 CLK2 (in), D13 I/OB5 <13> (io), D14 I/OB7 <19> (io), D15 I/OB7 <15> (io), L3 TOE (in), M19 GOE1 (in), M20 QIOCLK1 (in), N1 GOE3 (in), N2 QIOCLK3 (in), P3 SET/RESET (in), P18 CLK1 (in), R4 I/OG0 <10> (io), R17 I/OG0 <13> (io), T4 I/OG0 <11> (io), T17 I/OG0 <18> (io), U3 I/OG0 <9> (io), U5 TDI (in), U6 I/OB1 <4> (io), U7 I/OB1 <5> (io), U8 I/OB1 <10> (io), U13 I/OB5 <9> (io), U14 I/OB7 <2> (io), U15 I/OB7 <6> (io), U16 I/OB7 <9> (io), U18 I/OG0 <16> (io), U19 I/OG0 <12> (io), V1 I/OG0 <8> (io), V3 I/OG0 <7> (io), V4 I/OG0 <0> (io), V5 I/OB1 <1> (io), V7 I/OB1 <7> (io), V8 I/OB1 <11> (io), V9 CLKEN (in), V10 I/OB5 <0> (io), V11 I/OB5 <4> (io), V12 I/OB5 <7> (io), V13 I/OB5 <10> (io), V14 I/OB7 <1> (io), V15 I/OB7 <5> (io), V16 I/OB7 <8> (io), V18 I/OG0 <17> (io), V19 I/OG0 <15> (io), V20 I/OG0 <14> (io), W1 I/OG0 <6> (io), W2 I/OG0 <5> (io), W3 I/OG0 <3> (io), W4 TMS (in), W5 I/OB1 <2> (io), W6 I/OB1 <6> (io), W10 I/OB5 <1> (io), W11 I/OB5 <3> (io), W12 I/OB5 <6> (io), W13 I/OB5 <8> (io), W14 I/OB7 <0> (io), W15 I/OB7 <4> (io), W17 I/OB7 <10> (io), W18 I/OG0 <22> (io), W20 I/OG0 <19> (io), Y1 I/OG0 <4> (io), Y2 I/OG0 <2> (io), Y3 I/OG0 <1> (io), Y4 I/OB1 <0> (io), Y5 I/OB1 <3> (io), Y6 I/OB1 <8> (io), Y7 I/OB1 <9> (io), Y8 QIOCLK0 (in), Y9 CLK0 (in), Y10 GOE0 (in), Y11 I/OB5 <2> (io), Y12 I/OB5 <5> (io), Y14 I/OB5 <11> (io), Y15 I/OB7 <3> (io), Y16 I/OB7 <7> (io), Y17 I/OB7 <11> (io), Y18 I/OG0 <23> (io), Y19 I/OG0 <21> (io), Y20 I/OG0 <20> (io)
part B pins: A1 I/OG5 <4> (io), A2 I/OG5 <3> (io), A3 I/OG5 <0> (io), A18 I/OG5 <23> (io), A19 I/OG5 <16> (io), B1 I/OG5 <5> (io), B2 I/OG5 <1> (io), B3 I/OG5 <2> (io), B18 I/OG5 <22> (io), B19 I/OG5 <19> (io), B20 I/OG5 <15> (io), C1 I/OG5 <11> (io), C2 I/OG5 <9> (io), C3 I/OG5 <8> (io), C18 I/OG5 <20> (io), C19 I/OG5 <17> (io), C20 I/OG5 <14> (io), D1 I/OG5 <10> (io), D2 I/OG5 <7> (io), D3 I/OG5 <6> (io), D18 I/OG5 <18> (io), D19 I/OG5 <12> (io), D20 I/OG4 <12> (io), E1 I/OG4 <9> (io), E2 I/OG4 <10> (io), E3 I/OG4 <11> (io), E17 I/OG5 <21> (io), E18 I/OG5 <13> (io), E19 I/OG4 <14> (io), E20 I/OG4 <18> (io), F1 I/OG4 <6> (io), F2 I/OG4 <7> (io), F3 I/OG4 <5> (io), F4 I/OG4 <8> (io), F17 I/OG4 <13> (io), F18 I/OG4 <17> (io), F19 I/OG4 <19> (io), F20 I/OG4 <21> (io), G1 I/OG4 <1> (io), G2 I/OG4 <0> (io), G3 I/OG4 <3> (io), G4 I/OG4 <4> (io), G17 I/OG4 <15> (io), G18 I/OG4 <16> (io), G19 I/OG4 <23> (io), H1 I/OG3 <1> (io), H2 I/OG3 <0> (io), H3 I/OG4 <2> (io), H17 I/OG4 <20> (io), H18 I/OG4 <22> (io), H19 I/OG3 <22> (io), H20 I/OG3 <20> (io), J1 I/OG3 <4> (io), J2 I/OG3 <3> (io), J3 I/OG3 <2> (io), J18 I/OG3 <23> (io), J19 I/OG3 <21> (io), J20 I/OG3 <19> (io), K1 I/OG3 <7> (io), K2 I/OG3 <6> (io), K3 I/OG3 <5> (io), K18 I/OG3 <18> (io), K19 I/OG3 <17> (io), K20 I/OG3 <16> (io), L1 I/OG3 <9> (io), L2 I/OG3 <8> (io), L18 I/OG3 <15> (io), L19 I/OG3 <14> (io), L20 I/OG3 <13> (io), M2 I/OG3 <10> (io), M3 I/OG3 <11> (io), M18 I/OG3 <12> (io), N3 I/OG2 <10> (io), N4 I/OG2 <9> (io), N18 I/OG2 <12> (io), N19 I/OG2 <13> (io), N20 I/OG2 <14> (io), P1 I/OG2 <11> (io), P2 I/OG2 <8> (io), P4 I/OG2 <7> (io), P17 I/OG2 <16> (io), P19 I/OG2 <15> (io), P20 I/OG2 <17> (io), R1 I/OG2 <6> (io), R2 I/OG2 <5> (io), R3 I/OG2 <4> (io), R18 I/OG2 <20> (io), R19 I/OG2 <19> (io), R20 I/OG2 <18> (io), T1 I/OG2 <3> (io), T2 I/OG2 <2> (io), T3 I/OG2 <1> (io), T18 I/OG2 <23> (io), T19 I/OG2 <22> (io), T20 I/OG2 <21> (io), U1 I/OG2 <0> (io)
part C pins: A7 VCCIO (power), A8 VCCIO (power), A9 NC, A20 VCCIO (power), B16 VCCIO (power), C5 VCCIO (power), C12 VCCIO (power), D4 GND (power), D9 VCC (power), D10 VCC (power), D11 VCC (power), D12 VCC (power), D16 GND (power), D17 GND (power), E4 VCCIO (power), G20 VCCIO (power), H4 VCCIO (power), J4 VCC (power), J9 GND (power), J10 GND (power), J11 GND (power), J12 GND (power), J17 VCC (power), K4 VCC (power), K9 GND (power), K10 GND (power), K11 GND (power), K12 GND (power), K17 VCC (power), L4 VCC (power), L9 GND (power), L10 GND (power), L11 GND (power), L12 GND (power), L17 VCC (power), M1 VCCIO (power), M4 VCC (power), M9 GND (power), M10 GND (power), M11 GND (power), M12 GND (power), M17 VCC (power), N17 VCCIO (power), U2 VCCIO (power), U4 GND (power), U9 VCC (power), U10 VCC (power), U11 VCC (power), U12 VCC (power), U17 GND (power), U20 VCCIO (power), V2 VCCIO (power), V6 VCCIO (power), V17 NC, W7 VCCIO (power), W8 VCCIO (power), W9 NC, W16 VCCIO (power), W19 VCCIO (power), Y13 VCCIO (power)

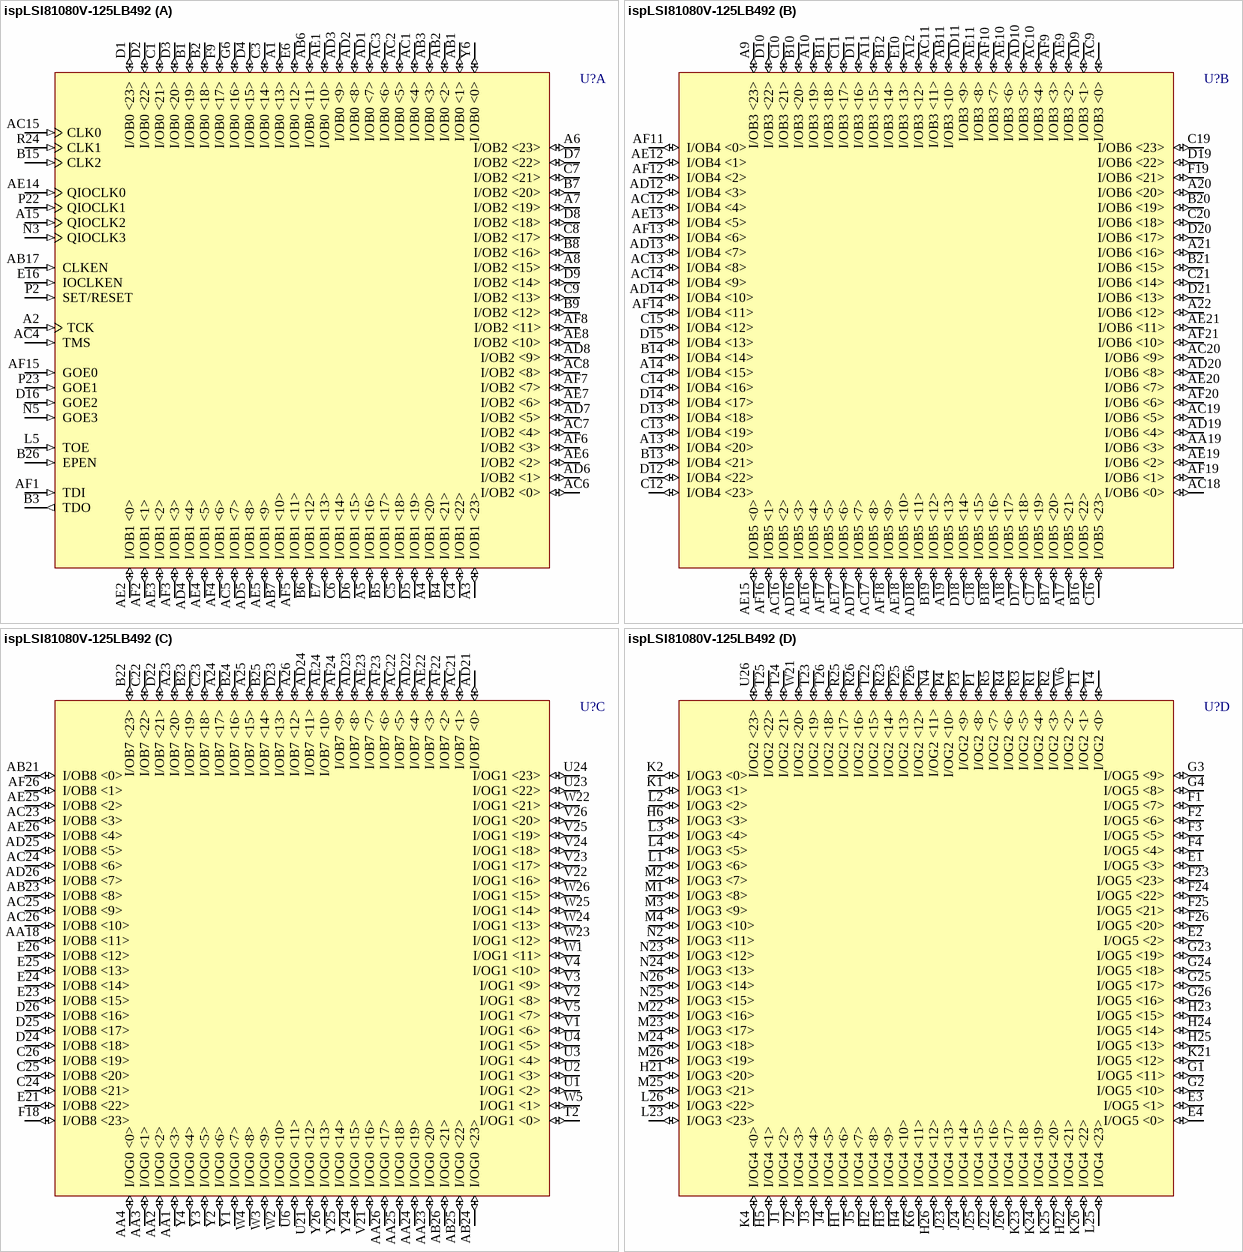
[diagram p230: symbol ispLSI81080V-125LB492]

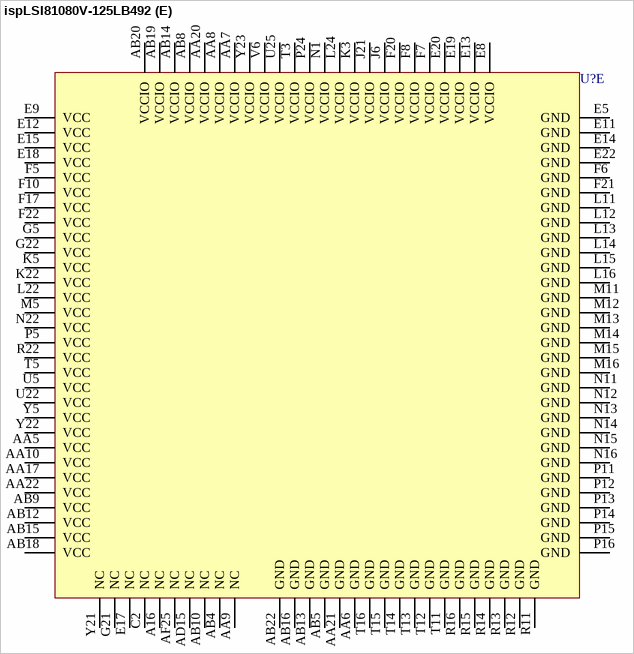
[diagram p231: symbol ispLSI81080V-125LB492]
